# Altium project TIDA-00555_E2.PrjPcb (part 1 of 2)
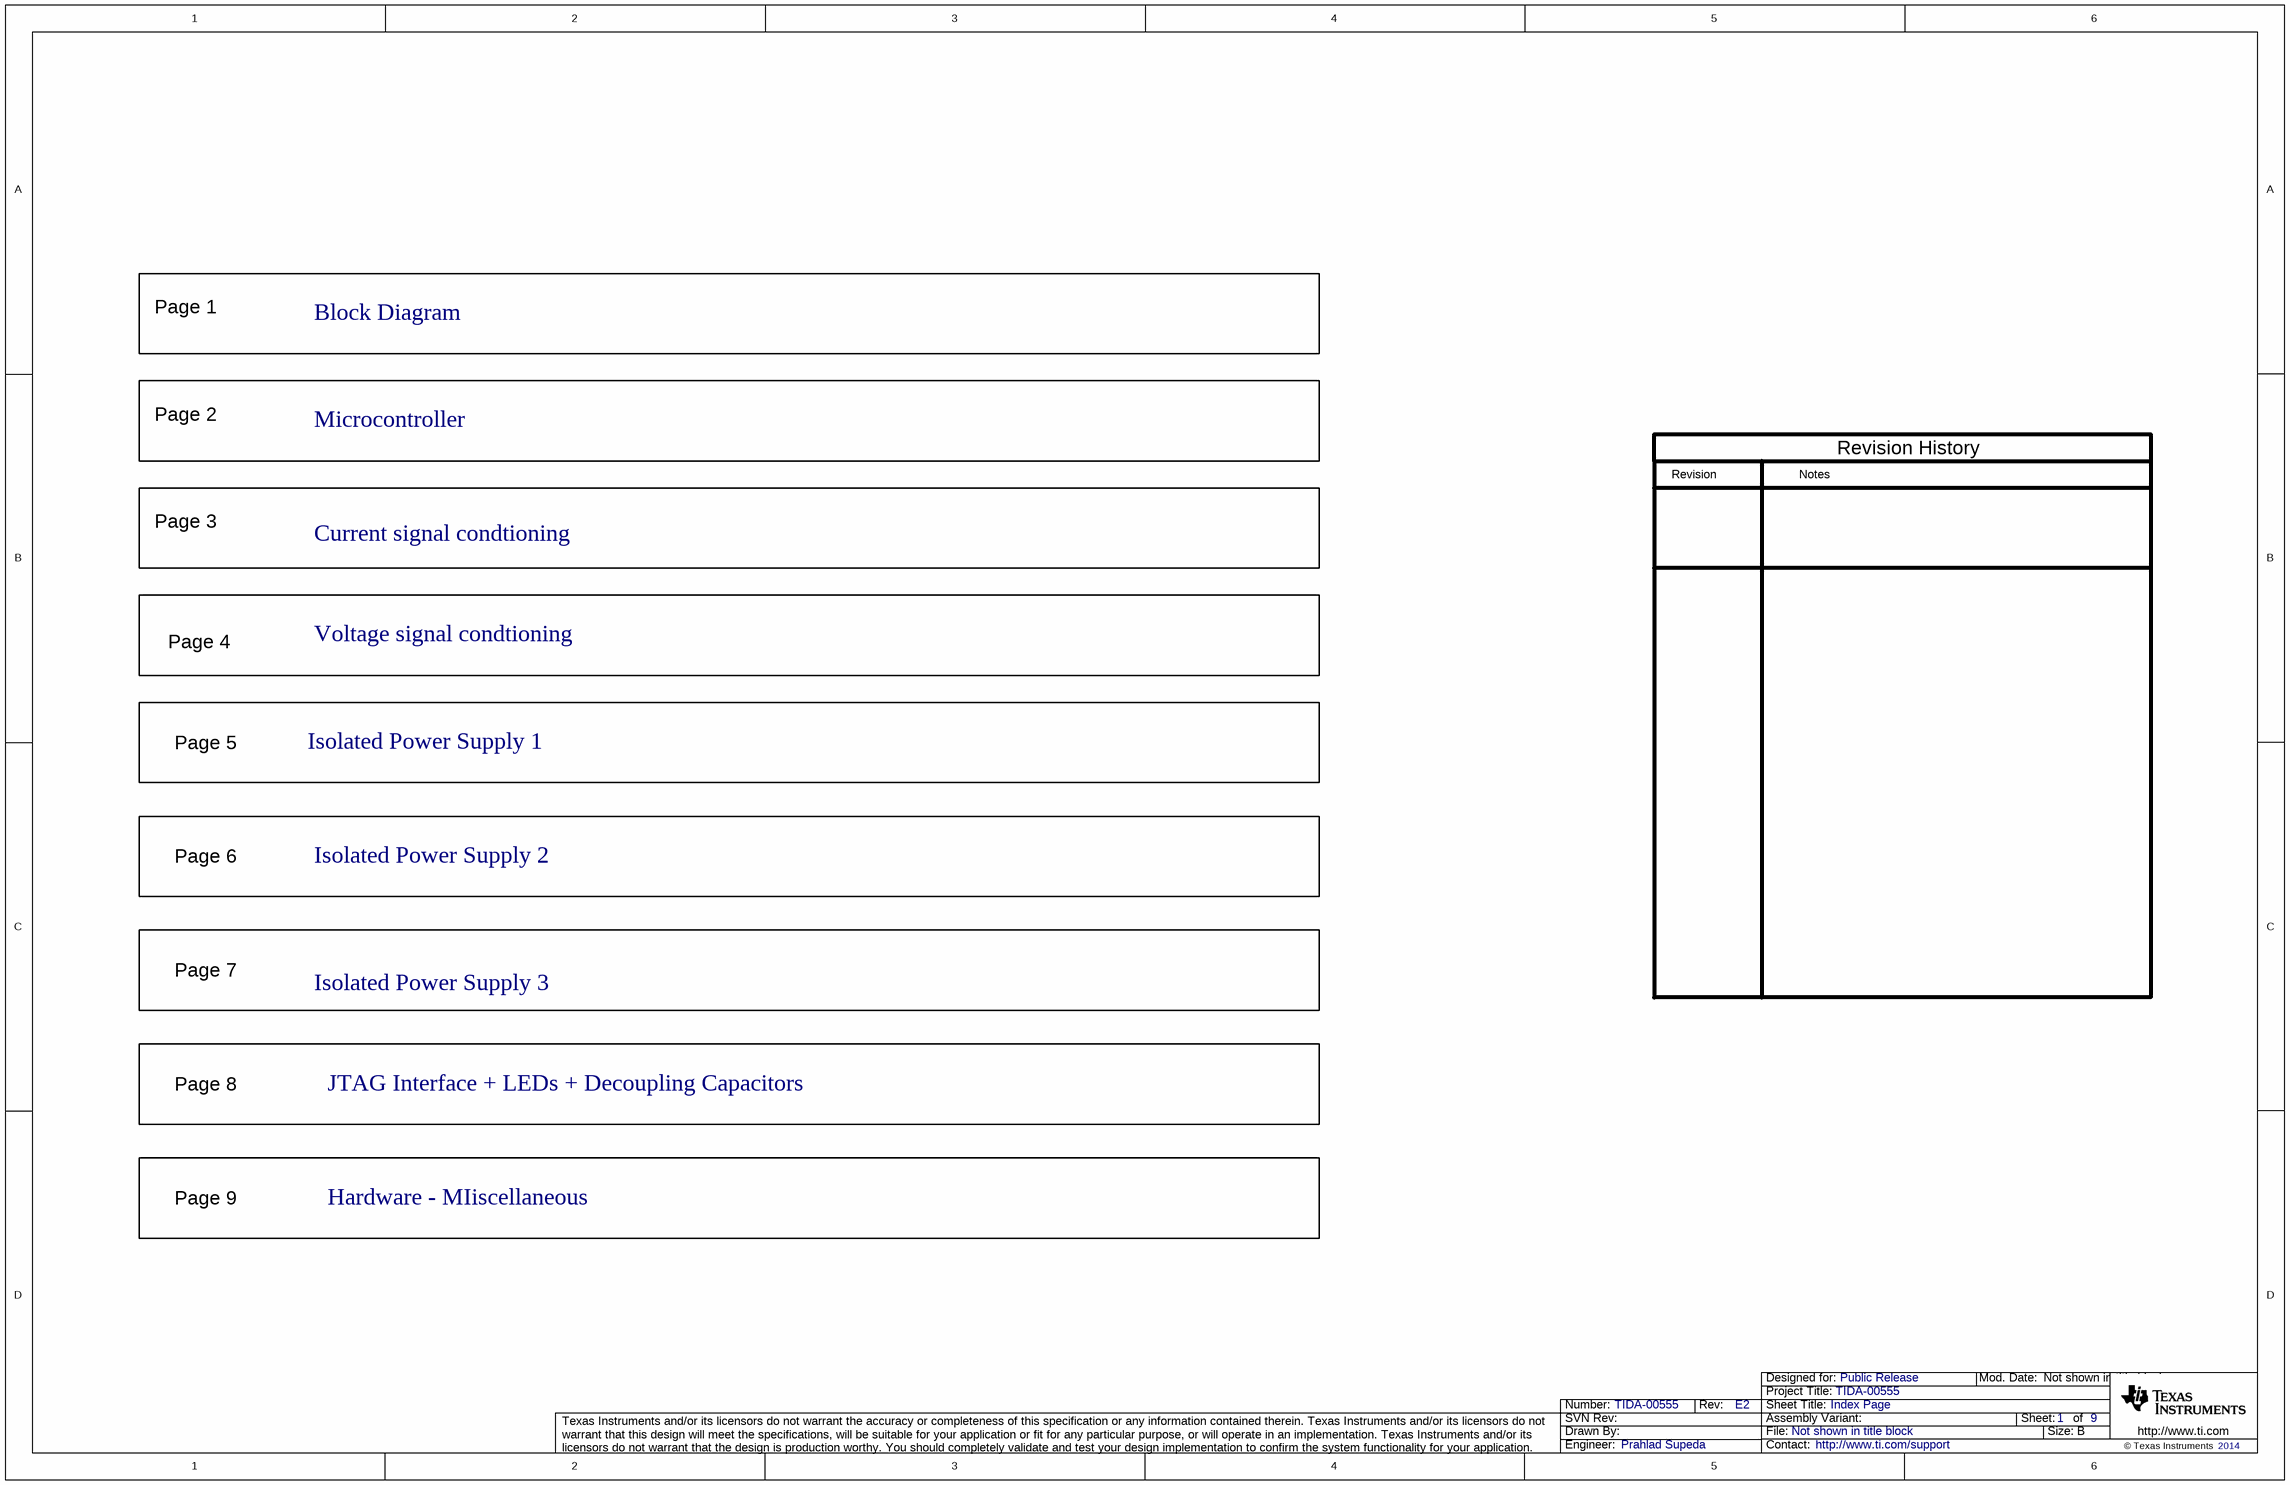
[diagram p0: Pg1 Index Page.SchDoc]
CopyrightYear: 2014; PCB_Layout: Anuradha; PCB_Rev: E2; PRJ_Customer: Public Release; PRJ_Engineer: Prahlad Supeda; PRJ_Number: TIDA-00555; PRJ_Title: TIDA-00555; SCH_Rev: E2; TechSupport: http://www.ti.com/support
9 sheets, 377 parts. Net scope: flat (ports and power ports of the same name join across sheets).
Board file: TIDA-00555_E2.PcbDoc
Sheets:
  Pg1 Index Page.SchDoc
  Pg2 Block Diagram.SchDoc
  Pg3-Microcontroller.SchDoc
  Pg4-Current  signal condtioning.SchDoc
  Pg5-Voltage signal condtioning.SchDoc
  Pg6-Power supply 1.SchDoc
  Pg7-Power supply 2.SchDoc
  Pg8.JTAG Interface + LEDs + Decoupling Capacitors.SchDoc
  Pg9-Hardware.SchDoc

## Sheet Pg1 Index Page.SchDoc: Index Page
size 431 x 279 mm; Date: Not shown in title block; ApprovedBy: Not shown in title block; CheckedBy: Not shown in title block; Author: Not shown in title block; CompanyName: Not shown in title block; Engineer: Not shown in title block; Organization: Not shown in title block; Address1: Not shown in title block; Address2: Not shown in title block; Address3: Not shown in title block; Address4: Not shown in title block; DocumentNumber: 1; Revision: Use project parameter SCH_Rev; SheetNumber: 1; SheetTotal: 9; PageSetup: Record=PageOptions¦CenterHorizontal=True¦CenterVertical=True¦PrintScale=1.00¦XCorrection=1.00¦YCorrection=1.00¦PrintKind=0¦BorderSize=5000000¦LeftOffset=0¦BottomOffset=0¦Orientation=2¦PaperLength=1000¦PaperWidth=1000¦Scale=100¦PaperSource=15¦PrintQuality=600¦MediaType=1¦DitherType=10¦PaperKind=Letter¦PrintScaleMode=1

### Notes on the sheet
- Page 1
- Block Diagram
- Page 2
- Microcontroller
- Revision
- Notes
- Revision History
- Page 3
- Current signal condtioning
- Page 4
- Voltage signal condtioning
- Page 5
- Isolated Power Supply 1
- Page 6
- Isolated Power Supply 2
- Page 7
- Isolated Power Supply 3
- Page 8
- JTAG Interface + LEDs + Decoupling Capacitors
- Page 9
- Hardware - MIiscellaneous

## Sheet Pg2 Block Diagram.SchDoc: Block Diagram
size 431 x 279 mm; Date: Not shown in title block; ApprovedBy: Not shown in title block; CheckedBy: Not shown in title block; Author: Not shown in title block; CompanyName: Not shown in title block; Engineer: Not shown in title block; Organization: Not shown in title block; Address1: Not shown in title block; Address2: Not shown in title block; Address3: Not shown in title block; Address4: Not shown in title block; DocumentNumber: 2; Revision: Use project parameter SCH_Rev; SheetNumber: 2; SheetTotal: 9; PageSetup: Record=PageOptions¦CenterHorizontal=True¦CenterVertical=True¦PrintScale=1.00¦XCorrection=1.00¦YCorrection=1.00¦PrintKind=0¦BorderSize=5000000¦LeftOffset=0¦BottomOffset=0¦Orientation=2¦PaperLength=1000¦PaperWidth=1000¦Scale=100¦PaperSource=15¦PrintQuality=600¦MediaType=1¦DitherType=10¦PaperKind=Letter¦PrintScaleMode=1
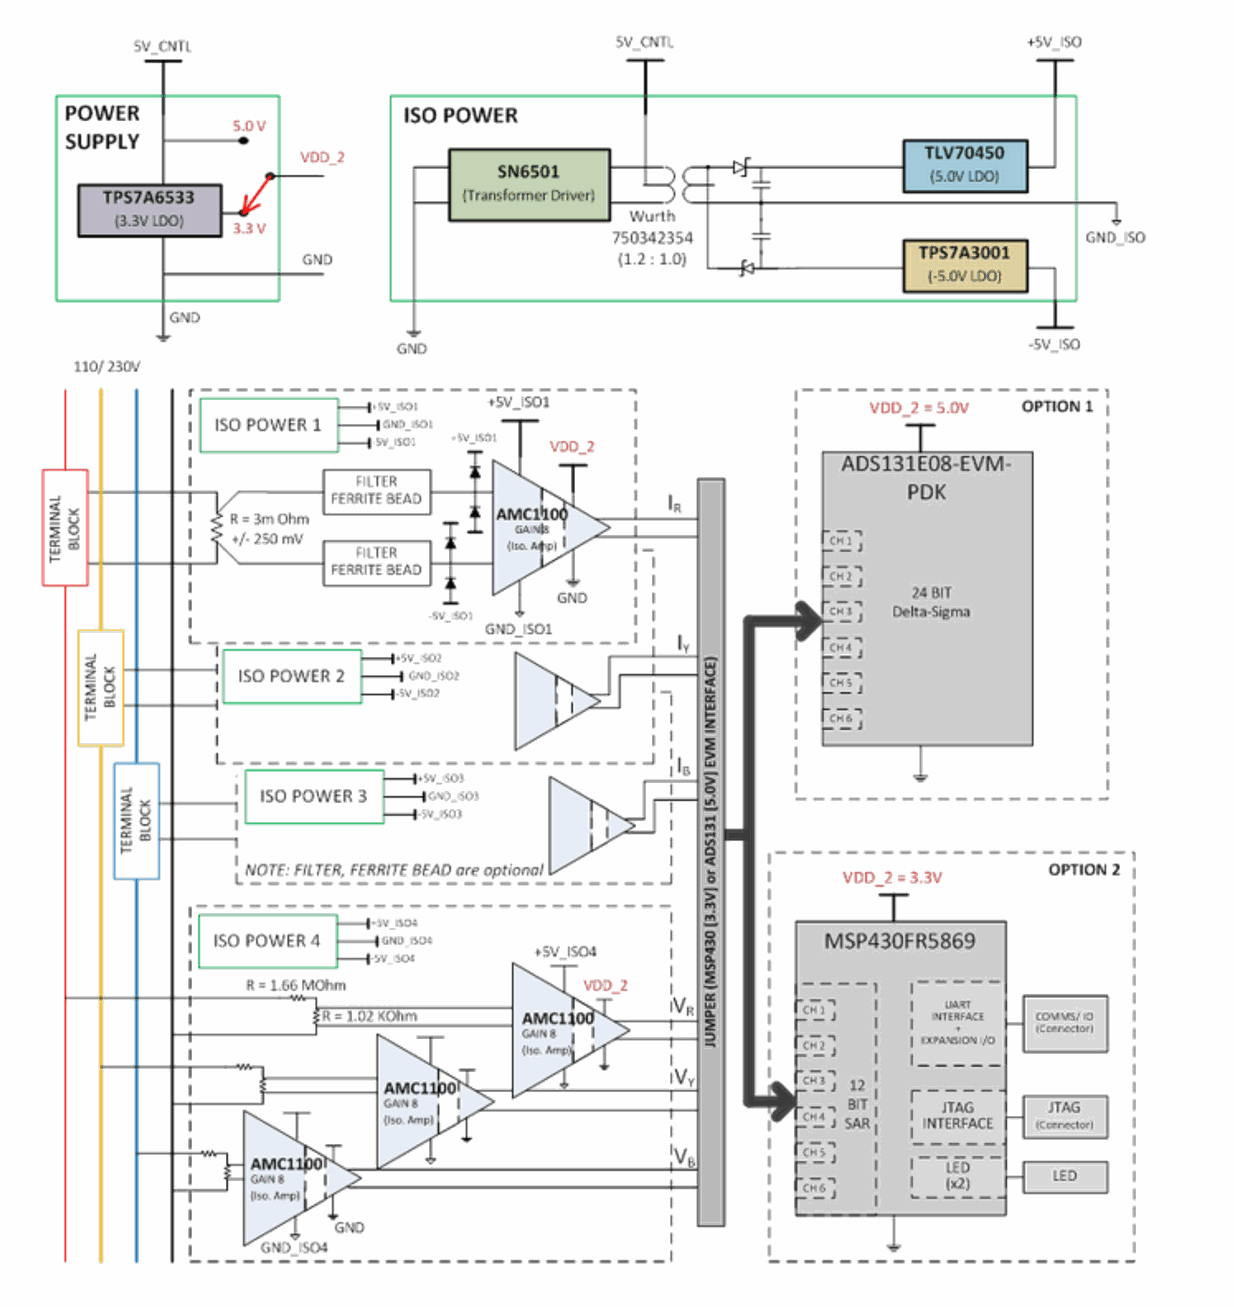
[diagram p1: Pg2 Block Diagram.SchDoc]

## Sheet Pg3-Microcontroller.SchDoc: MSP430F6779 + Crystal
size 431 x 279 mm; Date: Not shown in title block; ApprovedBy: Not shown in title block; CheckedBy: Not shown in title block; Author: Not shown in title block; CompanyName: Not shown in title block; Engineer: Not shown in title block; Organization: Not shown in title block; Address1: Not shown in title block; Address2: Not shown in title block; Address3: Not shown in title block; Address4: Not shown in title block; DocumentNumber: 6; Revision: Use project parameter SCH_Rev; SheetNumber: 3; SheetTotal: 9; PageSetup: Record=PageOptions¦CenterHorizontal=True¦CenterVertical=True¦PrintScale=1.00¦XCorrection=1.00¦YCorrection=1.00¦PrintKind=0¦BorderSize=5000000¦LeftOffset=0¦BottomOffset=0¦Orientation=2¦PaperLength=1000¦PaperWidth=1000¦Scale=100¦PaperSource=15¦PrintQuality=600¦MediaType=1¦DitherType=10¦PaperKind=Letter¦PrintScaleMode=1
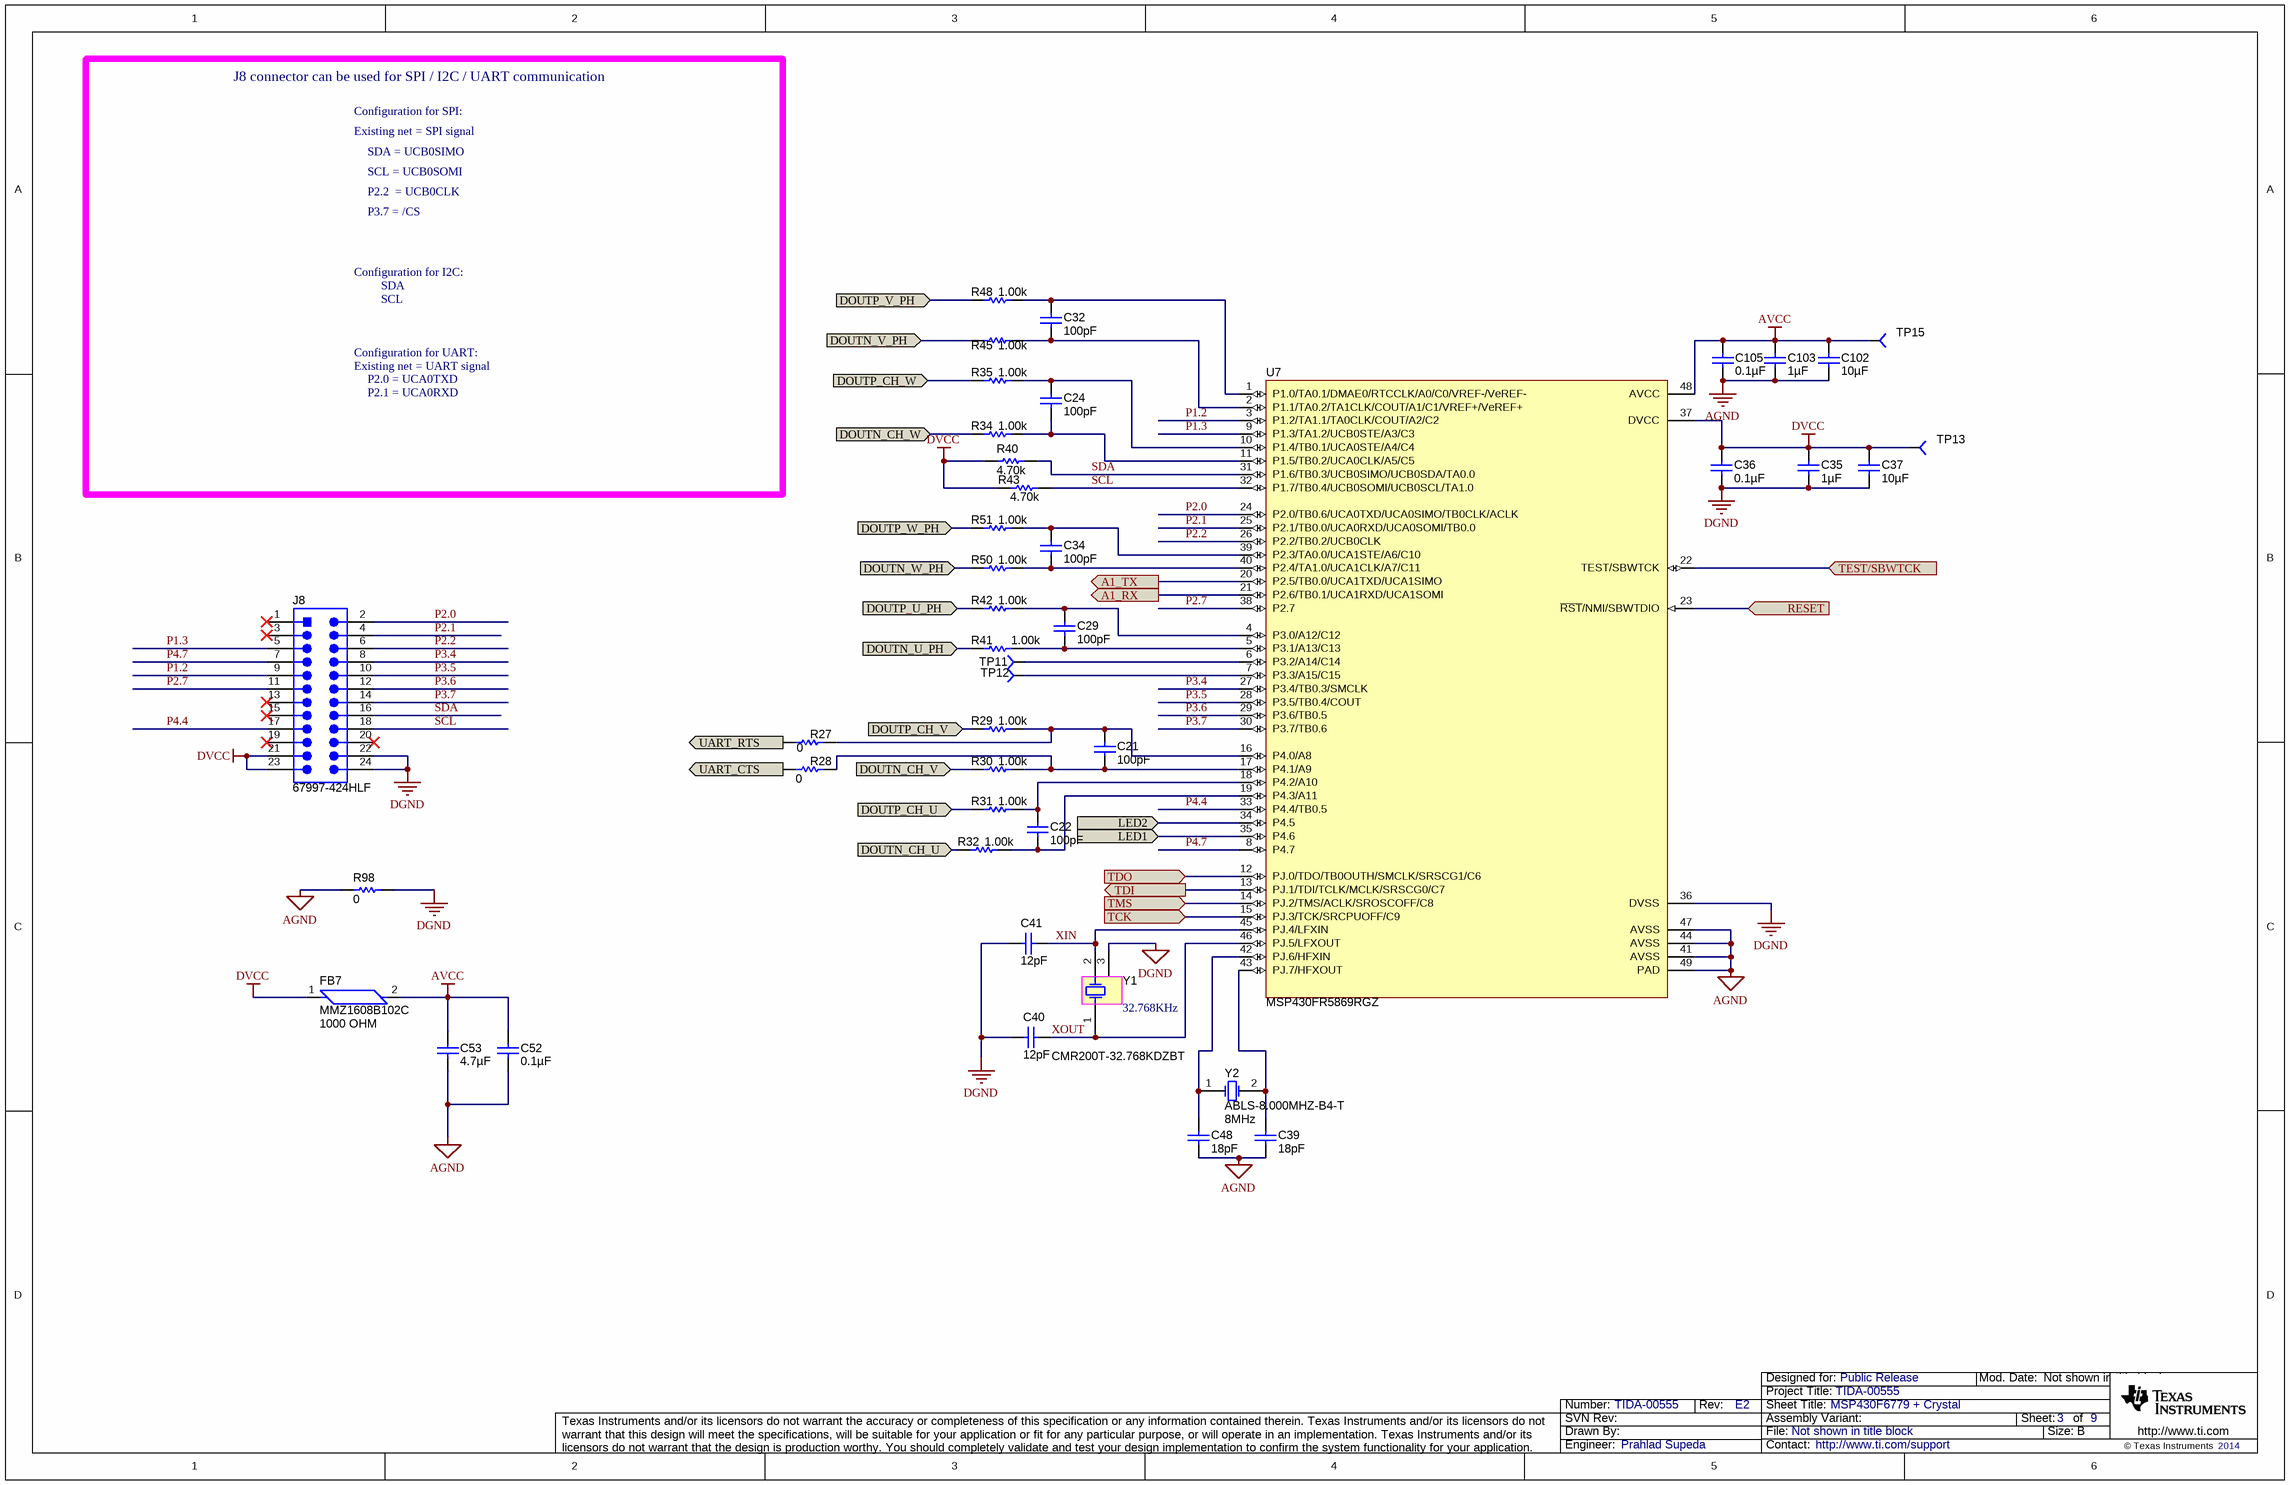
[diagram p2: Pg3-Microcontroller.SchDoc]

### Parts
C21  ValueDisplayed: 100pF  [0603]  (hidden comment: C0603C101J5GAC)
C22  ValueDisplayed: 100pF  [0603]  (hidden comment: C0603C101J5GAC)
C24  ValueDisplayed: 100pF  [0603]  (hidden comment: C0603C101J5GAC)
C29  ValueDisplayed: 100pF  [0603]  (hidden comment: C0603C101J5GAC)
C32  ValueDisplayed: 100pF  [0603]  (hidden comment: C0603C101J5GAC)
C34  ValueDisplayed: 100pF  [0603]  (hidden comment: C0603C101J5GAC)
C35  ValueDisplayed: 1µF  [0603]  (hidden comment: GRM188R71C105KA12D)
C36  ValueDisplayed: 0.1µF  [0603]  (hidden comment: 0603YC104JAT2A)
C37  ValueDisplayed: 10µF  [0603]  (hidden comment: GRM188R61E106MA73)
C39  ValueDisplayed: 18pF  [0603]  (hidden comment: GRM1885C1H180JA01D)
C40  ValueDisplayed: 12pF  [0603]  (hidden comment: 06035A120JAT2A)
C41  ValueDisplayed: 12pF  [0603]  (hidden comment: 06035A120JAT2A)
C48  ValueDisplayed: 18pF  [0603]  (hidden comment: GRM1885C1H180JA01D)
C52  ValueDisplayed: 0.1µF  [0603]  (hidden comment: 06033C104JAT2A)
C53  ValueDisplayed: 4.7µF  [0603]  (hidden comment: 0603ZD475KAT2A)
C102  ValueDisplayed: 10µF  [0603]  (hidden comment: GRM188R61E106MA73)
C103  ValueDisplayed: 1µF  [0603]  (hidden comment: GRM188R71C105KA12D)
C105  ValueDisplayed: 0.1µF  [0603]  (hidden comment: 0603YC104JAT2A)
FB7  MMZ1608B102C  value 1000 OHM  [FB0603]
J8  67997-424HLF  [TSW-112-07-G-D]
R27  value 0  [0603]  (hidden comment: CRCW06030000Z0EA)
R28  value 0  [0603]  (hidden comment: CRCW06030000Z0EA)
R29  ValueDisplayed: 1.00k  [0603]  (hidden comment: RG1608P-102-B-T5)
R30  ValueDisplayed: 1.00k  [0603]  (hidden comment: RG1608P-102-B-T5)
R31  ValueDisplayed: 1.00k  [0603]  (hidden comment: RG1608P-102-B-T5)
R32  ValueDisplayed: 1.00k  [0603]  (hidden comment: RG1608P-102-B-T5)
R34  ValueDisplayed: 1.00k  [0603]  (hidden comment: RG1608P-102-B-T5)
R35  ValueDisplayed: 1.00k  [0603]  (hidden comment: RG1608P-102-B-T5)
R40  value 4.70k  [0603]  (hidden comment: RC0603FR-074K7L)
R41  ValueDisplayed: 1.00k  [0603]  (hidden comment: RG1608P-102-B-T5)
R42  ValueDisplayed: 1.00k  [0603]  (hidden comment: RG1608P-102-B-T5)
R43  value 4.70k  [0603]  (hidden comment: RC0603FR-074K7L)
R45  ValueDisplayed: 1.00k  [0603]  (hidden comment: RG1608P-102-B-T5)
R48  ValueDisplayed: 1.00k  [0603]  (hidden comment: RG1608P-102-B-T5)
R50  ValueDisplayed: 1.00k  [0603]  (hidden comment: RG1608P-102-B-T5)
R51  ValueDisplayed: 1.00k  [0603]  (hidden comment: RG1608P-102-B-T5)
R98  value 0  [0805_HV]  (hidden comment: CRCW08050000Z0EA)
TP11  TP-040_RND  [TP-040_RND]  (value not drawn)
TP12  TP-040_RND  [TP-040_RND]  (value not drawn)
TP13  TP-040_RND  [TP-040_RND]  (value not drawn)
TP15  TP-040_RND  [TP-040_RND]  (value not drawn)
U7  MSP430FR5869RGZ  [RGZ0048B]
Y1  CMR200T-32.768KDZBT  Frequency: 32.768KHz  [XTAL_CMR200T]
Y2  ABLS-8.000MHZ-B4-T  Frequency: 8MHz  [XTAL_CSM-7X]

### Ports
A1_RX (out), A1_TX (out), DOUTN_CH_U (in), DOUTN_CH_V (in), DOUTN_CH_W (in), DOUTN_U_PH (in), DOUTN_V_PH (in), DOUTN_W_PH (in), DOUTP_CH_U (in), DOUTP_CH_V (in), DOUTP_CH_W (in), DOUTP_U_PH (in), DOUTP_V_PH (in), DOUTP_W_PH (in), LED1 (in), LED2 (in), RESET, TCK, TDI (out), TDO, TEST/SBWTCK, TMS, UART_CTS, UART_RTS

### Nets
AGND: C39.2 C48.2 C52.2 C53.2 C102.2 C103.2 C105.2 R98.1 U7.41(AVSS) U7.44(AVSS) U7.47(AVSS) U7.49(PAD)
AVCC: C52.1 C53.1 C102.1 C103.1 C105.1 FB7.2 TP15.1 U7.48(AVCC)
DGND: C35.2 C36.2 C37.2 C40.2 C41.2 J8.22 J8.24 R98.2 U7.36(DVSS) Y1.3
DVCC: C35.1 C36.1 C37.1 FB7.1 J8.21 J8.23 R40.1 R43.1 TP13.1 U7.37(DVCC)
A1_RX: U7.21(P2.6/TB0.1/UCA1RXD/UCA1SOMI) ; port A1_RX
A1_TX: U7.20(P2.5/TB0.0/UCA1TXD/UCA1SIMO) ; port A1_TX
DOUTN_CH_U: R32.1 ; port DOUTN_CH_U
DOUTN_CH_V: R30.1 ; port DOUTN_CH_V
DOUTN_CH_W: R34.1 ; port DOUTN_CH_W
DOUTN_U_PH: R41.1 ; port DOUTN_U_PH
DOUTN_V_PH: R45.1 ; port DOUTN_V_PH
DOUTN_W_PH: R50.1 ; port DOUTN_W_PH
DOUTP_CH_U: R31.1 ; port DOUTP_CH_U
DOUTP_CH_V: R29.1 ; port DOUTP_CH_V
DOUTP_CH_W: R35.1 ; port DOUTP_CH_W
DOUTP_U_PH: R42.1 ; port DOUTP_U_PH
DOUTP_V_PH: R48.1 ; port DOUTP_V_PH
DOUTP_W_PH: R51.1 ; port DOUTP_W_PH
LED1: U7.35(P4.6) ; port LED1
LED2: U7.34(P4.5) ; port LED2
P1.2: J8.9 U7.3(P1.2/TA1.1/TA0CLK/COUT/A2/C2)
P1.3: J8.5 U7.9(P1.3/TA1.2/UCB0STE/A3/C3)
P2.0: J8.2 U7.24(P2.0/TB0.6/UCA0TXD/UCA0SIMO/TB0CLK/ACLK)
P2.1: J8.4 U7.25(P2.1/TB0.0/UCA0RXD/UCA0SOMI/TB0.0)
P2.2: J8.6 U7.26(P2.2/TB0.2/UCB0CLK)
P2.7: J8.11 U7.38(P2.7)
P3.4: J8.8 U7.27(P3.4/TB0.3/SMCLK)
P3.5: J8.10 U7.28(P3.5/TB0.4/COUT)
P3.6: J8.12 U7.29(P3.6/TB0.5)
P3.7: J8.14 U7.30(P3.7/TB0.6)
P4.4: J8.17 U7.33(P4.4/TB0.5)
P4.7: J8.7 U7.8(P4.7)
RESET: U7.23(~{RST}/NMI/SBWTDIO) ; port RESET
SCL: J8.18 R43.2 U7.32(P1.7/TB0.4/UCB0SOMI/UCB0SCL/TA1.0)
SDA: J8.16 R40.2 U7.31(P1.6/TB0.3/UCB0SIMO/UCB0SDA/TA0.0)
TCK: U7.15(PJ.3/TCK/SRCPUOFF/C9) ; port TCK
TDI: U7.13(PJ.1/TDI/TCLK/MCLK/SRSCG0/C7) ; port TDI
TDO: U7.12(PJ.0/TDO/TB0OUTH/SMCLK/SRSCG1/C6) ; port TDO
TEST/SBWTCK: U7.22(TEST/SBWTCK) ; port TEST/SBWTCK
TMS: U7.14(PJ.2/TMS/ACLK/SROSCOFF/C8) ; port TMS
UART_CTS: R28.1 ; port UART_CTS
UART_RTS: R27.1 ; port UART_RTS
XIN: C41.1 U7.45(PJ.4/LFXIN) Y1.2
XOUT: C40.1 U7.46(PJ.5/LFXOUT) Y1.1
NetC21_1: C21.1 R28.2 R30.2 U7.17(P4.1/A9)
NetC21_2: C21.2 R27.2 R29.2 U7.16(P4.0/A8)
NetC22_1: C22.1 R32.2 U7.19(P4.3/A11)
NetC22_2: C22.2 R31.2 U7.18(P4.2/A10)
NetC24_1: C24.1 R34.2 U7.11(P1.5/TB0.2/UCA0CLK/A5/C5)
NetC24_2: C24.2 R35.2 U7.10(P1.4/TB0.1/UCA0STE/A4/C4)
NetC29_1: C29.1 R41.2 U7.5(P3.1/A13/C13)
NetC29_2: C29.2 R42.2 U7.4(P3.0/A12/C12)
NetC32_1: C32.1 R45.2 U7.2(P1.1/TA0.2/TA1CLK/COUT/A1/C1/VREF+/VeREF+)
NetC32_2: C32.2 R48.2 U7.1(P1.0/TA0.1/DMAE0/RTCCLK/A0/C0/VREF-/VeREF-)
NetC34_1: C34.1 R50.2 U7.40(P2.4/TA1.0/UCA1CLK/A7/C11)
NetC34_2: C34.2 R51.2 U7.39(P2.3/TA0.0/UCA1STE/A6/C10)
NetC39_1: C39.1 U7.43(PJ.7/HFXOUT) Y2.2(OSC2)
NetC48_1: C48.1 U7.42(PJ.6/HFXIN) Y2.1(OSC1)
NetTP11_1: TP11.1 U7.6(P3.2/A14/C14)
NetTP12_1: TP12.1 U7.7(P3.3/A15/C15)

Not connected (* = marked no-connect by the designer): J8 1* 3* 13* 15* 19* 20*

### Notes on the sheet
- J8 connector can be used for SPI / I2C / UART communication
- Configuration for SPI:
- Existing net = SPI signal
- SDA = UCB0SIMO
- SCL = UCB0SOMI
- P2.2  = UCB0CLK
- P3.7 = /CS
- Configuration for I2C:
- SDA
- SCL
- Configuration for UART:
- Existing net = UART signal
- P2.0 = UCA0TXD
- P2.1 = UCA0RXD

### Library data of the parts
C21 C22 C24 C29 C32 C34 = C0603C101J5GAC: CAP, CERM, 100 pF, 50 V, +/- 5%, C0G/NP0, 0603; Manufacturer: Kemet; Polarized: N; CompType: Capacitor; Value: 100pF; U/M: EA; Cap_F: 0.0000000001; Tolerance_%: 5; Value1: Unknown; VDC_V: 50; Value2: 50V; TaMin_C: -55; TaMax_C: 125
C35 C103 = GRM188R71C105KA12D: CAP, CERM, 1 µF, 16 V, +/- 10%, X7R, 0603; Manufacturer: MuRata; Polarized: N; CompType: Capacitor; Value: 1uF; U/M: EA; Cap_F: 0.000001; Tolerance_%: 10; ESR_ohm: 0.011; Value1: 0.011 ohm; VDC_V: 16; Value2: 16V; TaMin_C: -55; TaMax_C: 125
C36 C105 = 0603YC104JAT2A: CAP, CERM, 0.1 µF, 16 V, +/- 5%, X7R, 0603; Manufacturer: AVX; Polarized: N; CompType: Capacitor; Value: 0.1uF; U/M: EA; Cap_F: 0.0000001; Tolerance_%: 5; ESR_ohm: 0.039; Value1: 0.039 ohm; VDC_V: 16; Value2: 16V; TaMin_C: -55; TaMax_C: 125
C37 C102 = GRM188R61E106MA73: CAP, CERM, 10uF, 25V, +/-20%, X5R, 0603; Manufacturer: MuRata; Polarized: N; CompType: Capacitor; U/M: EA; Cap_F: 0.00001; Tolerance_%: 20; Value1: Unknown; VDC_V: 25; TaMin_C: -55; TaMax_C: 85
C39 C48 = GRM1885C1H180JA01D: CAP, CERM, 18pF, 50V, +/-5%, C0G/NP0, 0603; Manufacturer: MuRata; Polarized: N; CompType: Capacitor; U/M: EA; Cap_F: 0.000000000018; Tolerance_%: 5; Value1: Unknown; VDC_V: 50; TaMin_C: -55; TaMax_C: 125
C40 C41 = 06035A120JAT2A: CAP, CERM, 12pF, 50V, +/-5%, C0G/NP0, 0603; Manufacturer: AVX; Polarized: N; CompType: Capacitor; U/M: EA; Cap_F: 0.000000000012; Tolerance_%: 5; ESR_Ohm: 0.363; Value1: 0.363 ohm; VDC_V: 50; TaMin_C: -55; TaMax_C: 125
C52 = 06033C104JAT2A: CAP, CERM, 0.1uF, 25V, +/-5%, X7R, 0603; Manufacturer: AVX; Polarized: N; CompType: Capacitor; U/M: EA; Cap_F: 0.0000001; Tolerance_%: 5; ESR_Ohm: 0.05; Value1: 0.05 ohm; VDC_V: 25; TaMin_C: -55; TaMax_C: 125
C53 = 0603ZD475KAT2A: CAP, CERM, 4.7uF, 10V, +/-10%, X5R, 0603; Manufacturer: AVX; Polarized: N; CompType: Capacitor; U/M: EA; Cap_F: 0.0000047; Tolerance_%: 10; Value1: Unknown; TaMin_C: -55; TaMax_C: 85
FB7 = MMZ1608B102C: FERRITE CHIP 1000 OHM 300MA 0603; Manufacturer: TDK Corporation; CompType: Ferrite Bead
J8 = TSW-112-07-G-D: Header, TH, 100mil, 12x2, Gold plated, 230 mil above insulator; Manufacturer: FCI; SymbolCreator: a0412235; U/M: EA
R27 R28 = CRCW06030000Z0EA: RES, 0 ohm, 5%, 0.1W, 0603; Manufacturer: Vishay-Dale; CompType: Resistor; Value_Code: 0000; Tolerance_%: 5; Power_W: 0.1; VDC_V: 75; TempCo: 200 ppm/C; EIA_Code: E24; U/M: EA
R29-R32 R34 R35 R41 R42 R45 R48 R50 R51 = RG1608P-102-B-T5: RES, 1.00 k, 0.1%, 0.1 W, 0603; Manufacturer: Susumu Co Ltd; CompType: Resistor; Value: 1.00k; Res_ohm: 1000; Value_Code: 1k00; Tolerance_%: 0.1; Value2: 0.1W; VDC_V: 75; TempCo: 25 ppm/C; EIA_Code: E192; U/M: EA
R40 R43 = RC0603FR-074K7L: RES, 4.70k ohm, 1%, 0.1W, 0603; Manufacturer: Yageo America; CompType: Resistor; Res_ohm: 4700; Value_Code: 4k70; Tolerance_%: 1; Power_W: 0.1; VDC_V: 150; TempCo: 200 ppm/C; U/M: EA
R98 = CRCW0805330KJNEA: RES, 0 ohm, 5%, 0.125W, 0805; Manufacturer: Vishay-Dale; CompType: Resistor; Tolerance_%: 5; Power_W: 0.125; VDC_V: 150; TempCo: 200 ppm/C; EIA_Code: E24; U/M: EA
TP11-TP13 TP15 = TP-040_RND: Test Point, O.040 Hole; Manufacturer: STD; Value: STD
U7 = MSP430FR5969IRGZ: Mixed Signal Microcontroller, RGZ0048B; Manufacturer: Texas Instruments; SymbolCreator: a0411947; CompType: IC; U/M: EA
Y1 = CMR200T-32.768KDZBT: CRYSTAL, 32.768KHz, 6PF, +/- 20PPM, SMD-3P; Manufacturer: CITIZEN; SymbolCreator: x0199378
Y2 = ABLS-8.000MHZ-B4-T: Crystal, 8MHz, 18pF, SMD; Manufacturer: Abracon Corportation; SymbolCreator: a0412235; U/M: EA; TaMin_C: 0; TaMax_C: 70; Frequency Stability: ±50ppm

## Sheet Pg4-Current  signal condtioning.SchDoc: Analog Front End (Current) + Delfino Interface
size 431 x 279 mm; Date: Not shown in title block; ApprovedBy: Not shown in title block; CheckedBy: Not shown in title block; Author: Not shown in title block; CompanyName: Not shown in title block; Engineer: Not shown in title block; Organization: Not shown in title block; Address1: Not shown in title block; Address2: Not shown in title block; Address3: Not shown in title block; Address4: Not shown in title block; DocumentNumber: 3; Revision: Use project parameter SCH_Rev; SheetNumber: 4; SheetTotal: 9; PageSetup: Record=PageOptions¦CenterHorizontal=True¦CenterVertical=True¦PrintScale=0.62¦XCorrection=1.00¦YCorrection=1.00¦PrintKind=0¦BorderSize=5000000¦LeftOffset=0¦BottomOffset=0¦Orientation=2¦PaperLength=1000¦PaperWidth=1000¦Scale=100¦PaperSource=15¦PrintQuality=600¦MediaType=1¦DitherType=10¦PaperKind=Letter¦PrintScaleMode=1
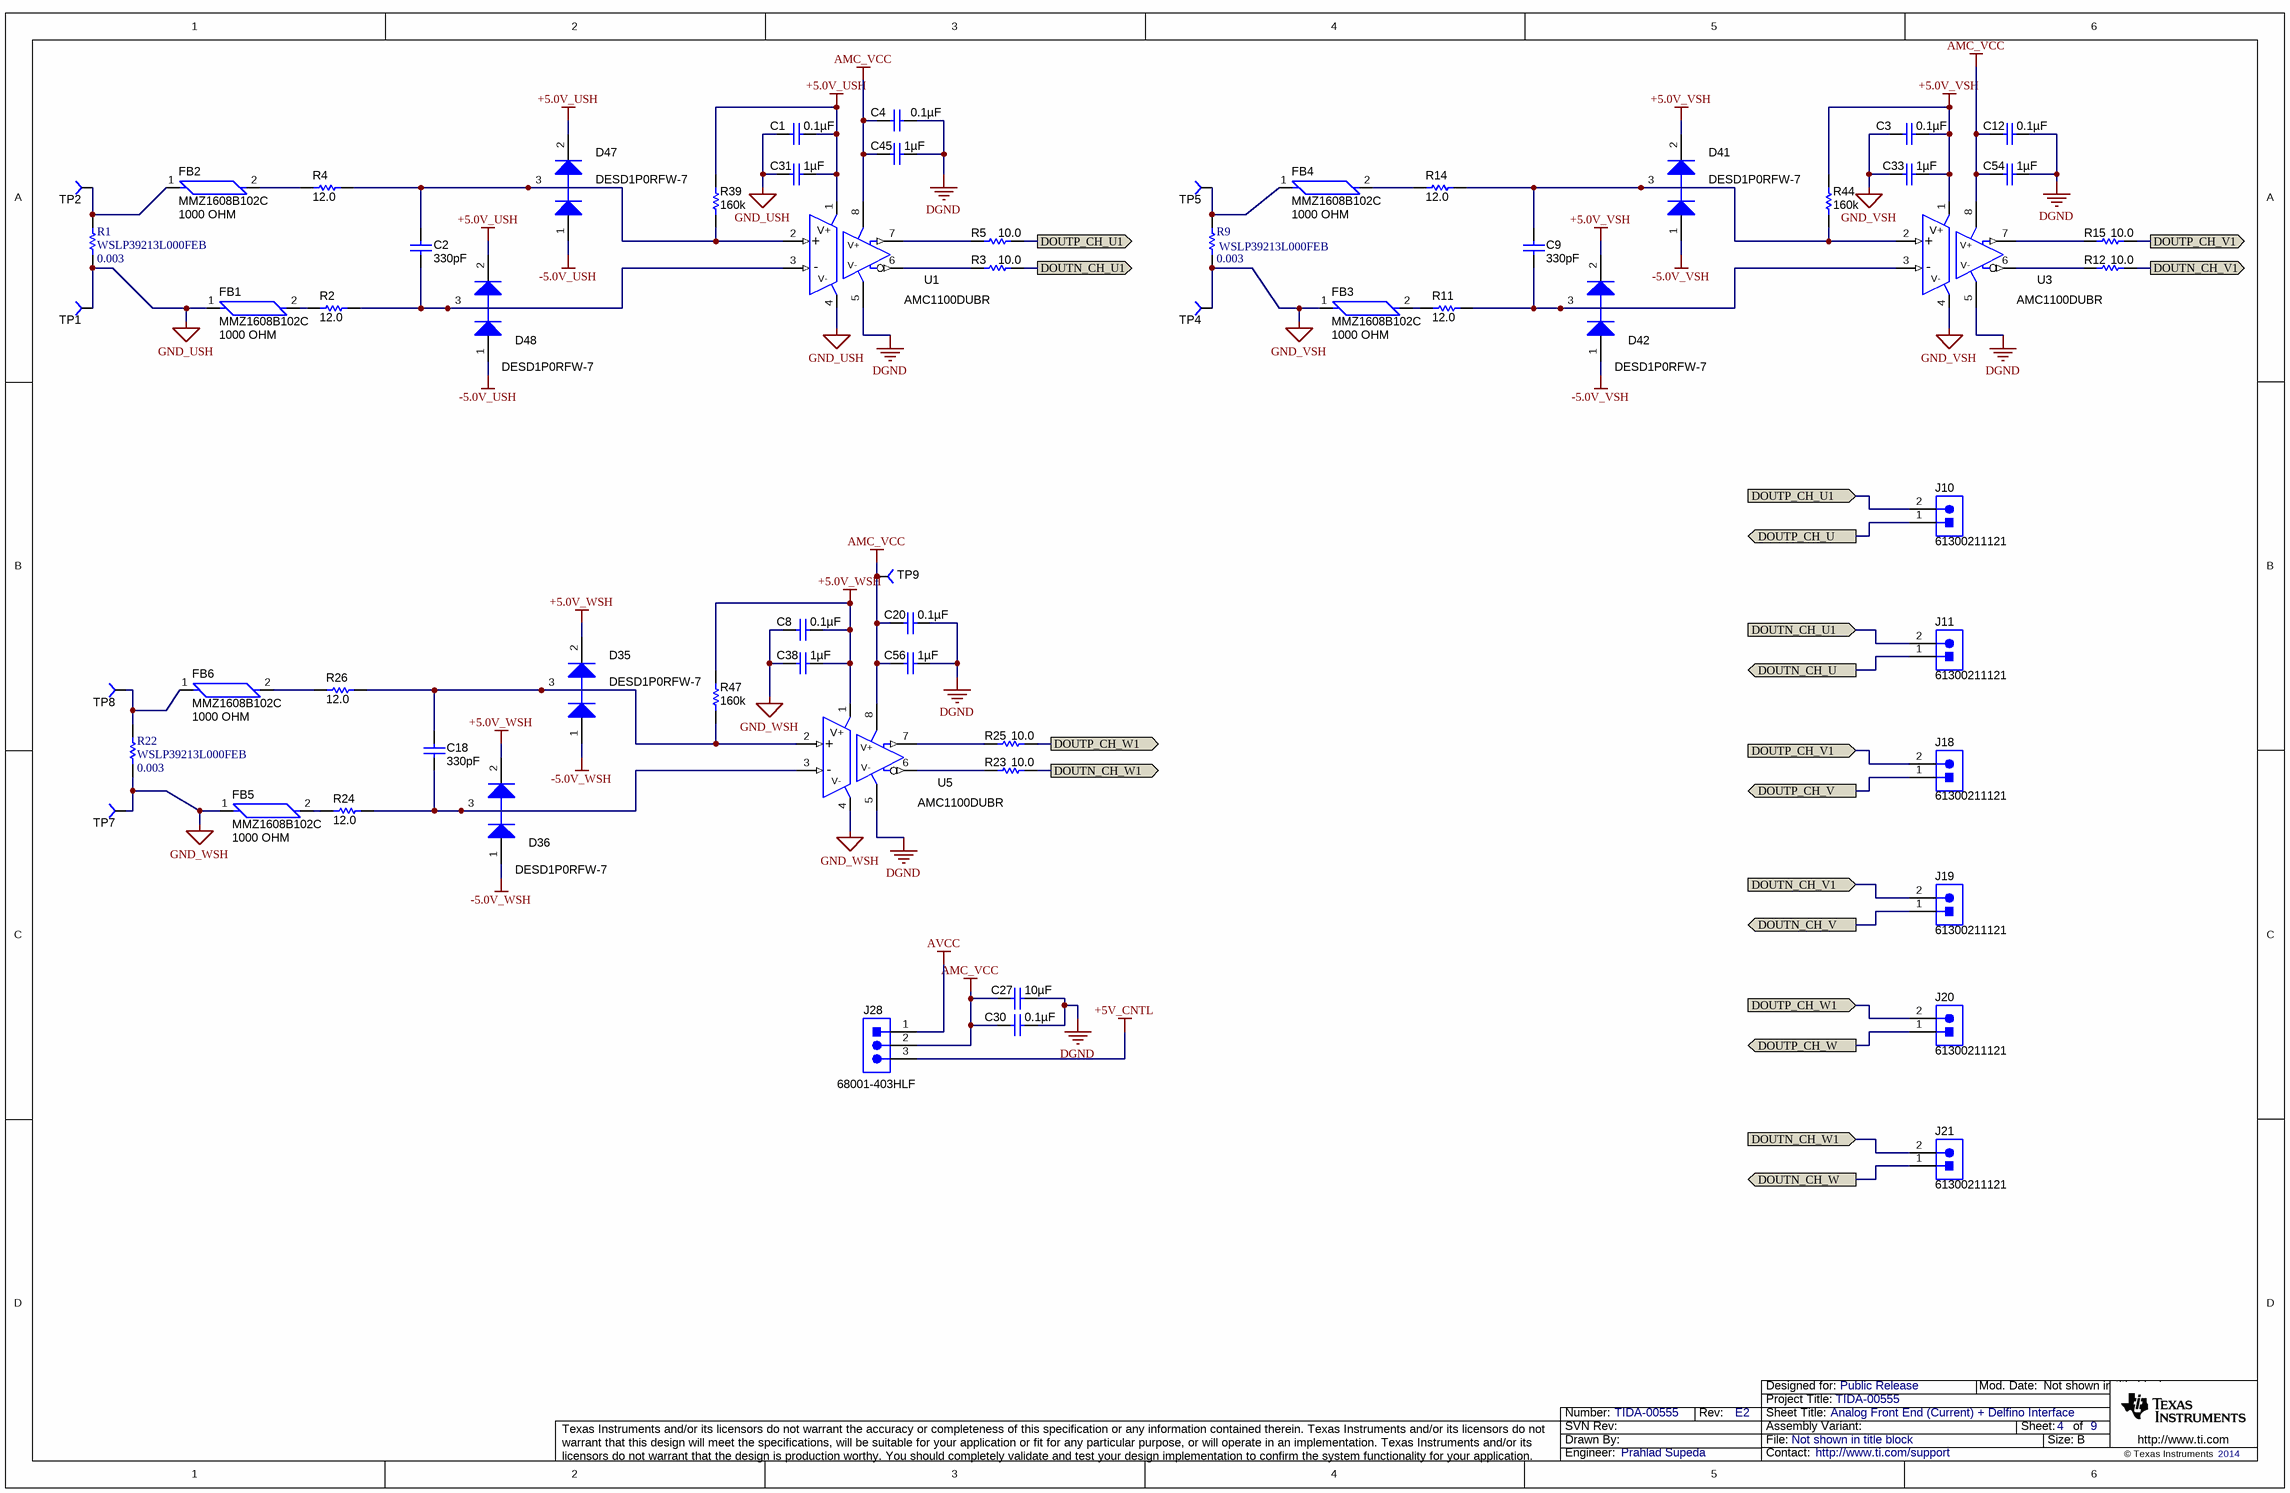
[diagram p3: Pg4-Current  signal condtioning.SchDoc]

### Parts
C1  ValueDisplayed: 0.1µF  [0603]
C2  ValueDisplayed: 330pF  [0805_HV]  (hidden comment: 08055A331KAT2A)
C3  ValueDisplayed: 0.1µF  [0603]
C4  ValueDisplayed: 0.1µF  [0603]
C8  ValueDisplayed: 0.1µF  [0603]
C9  ValueDisplayed: 330pF  [0805_HV]  (hidden comment: 08055A331KAT2A)
C12  ValueDisplayed: 0.1µF  [0603]
C18  ValueDisplayed: 330pF  [0805_HV]  (hidden comment: 08055A331KAT2A)
C20  ValueDisplayed: 0.1µF  [0603]
C27  ValueDisplayed: 10µF  [1210]
C30  ValueDisplayed: 0.1µF  [0603]
C31  ValueDisplayed: 1µF  [0603]  (hidden comment: GRM188R71C105KA12D)
C33  ValueDisplayed: 1µF  [0603]  (hidden comment: GRM188R71C105KA12D)
C38  ValueDisplayed: 1µF  [0603]  (hidden comment: GRM188R71C105KA12D)
C45  ValueDisplayed: 1µF  [0603]  (hidden comment: GRM188R71C105KA12D)
C54  ValueDisplayed: 1µF  [0603]  (hidden comment: GRM188R71C105KA12D)
C56  ValueDisplayed: 1µF  [0603]  (hidden comment: GRM188R71C105KA12D)
D35  value DESD1P0RFW-7  [SOT-323]
D36  value DESD1P0RFW-7  [SOT-323]
D41  value DESD1P0RFW-7  [SOT-323]
D42  value DESD1P0RFW-7  [SOT-323]
D47  value DESD1P0RFW-7  [SOT-323]
D48  value DESD1P0RFW-7  [SOT-323]
FB1  MMZ1608B102C  value 1000 OHM  [FB0603]
FB2  MMZ1608B102C  value 1000 OHM  [FB0603]
FB3  MMZ1608B102C  value 1000 OHM  [FB0603]
FB4  MMZ1608B102C  value 1000 OHM  [FB0603]
FB5  MMZ1608B102C  value 1000 OHM  [FB0603]
FB6  MMZ1608B102C  value 1000 OHM  [FB0603]
J10  61300211121  [WURTH_61300211121]
J11  61300211121  [WURTH_61300211121]
J18  61300211121  [WURTH_61300211121]
J19  61300211121  [WURTH_61300211121]
J20  61300211121  [WURTH_61300211121]
J21  61300211121  [WURTH_61300211121]
J28  68001-403HLF  [HDR1X3]
R1  WSLP39213L000FEB  value 0.003  [RC3921]
R2  ValueDisplayed: 12.0  [0603]  (hidden comment: RC0603FR-0712RL)
R3  value 10.0  [0603]
R4  ValueDisplayed: 12.0  [0603]  (hidden comment: RC0603FR-0712RL)
R5  value 10.0  [0603]
R9  WSLP39213L000FEB  value 0.003  [RC3921]
R11  ValueDisplayed: 12.0  [0603]  (hidden comment: RC0603FR-0712RL)
R12  value 10.0  [0603]
R14  ValueDisplayed: 12.0  [0603]  (hidden comment: RC0603FR-0712RL)
R15  value 10.0  [0603]
R22  WSLP39213L000FEB  value 0.003  [RC3921]
R23  value 10.0  [0603]
R24  ValueDisplayed: 12.0  [0603]  (hidden comment: RC0603FR-0712RL)
R25  value 10.0  [0603]
R26  ValueDisplayed: 12.0  [0603]  (hidden comment: RC0603FR-0712RL)
R39  ValueDisplayed: 160k  [0603]  (hidden comment: CRCW0603160KFKEA)
R44  ValueDisplayed: 160k  [0603]  (hidden comment: CRCW0603160KFKEA)
R47  ValueDisplayed: 160k  [0603]  (hidden comment: CRCW0603160KFKEA)
TP1  TP-5001-BLACK  [TH-40]  (value not drawn)
TP2  TP-5001-BLACK  [TH-40]  (value not drawn)
TP4  TP-5001-BLACK  [TH-40]  (value not drawn)
TP5  TP-5001-BLACK  [TH-40]  (value not drawn)
TP7  TP-5001-BLACK  [TH-40]  (value not drawn)
TP8  TP-5001-BLACK  [TH-40]  (value not drawn)
TP9  (no value)  [TP-040_RND]
U1  AMC1100DUBR  [DUB0008A_N]
U3  AMC1100DUBR  [DUB0008A_N]
U5  AMC1100DUBR  [DUB0008A_N]

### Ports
DOUTN_CH_U1 (in), DOUTN_CH_U1 (out), DOUTN_CH_U (out), DOUTN_CH_V1 (in), DOUTN_CH_V1 (out), DOUTN_CH_V (out), DOUTN_CH_W1 (in), DOUTN_CH_W1 (out), DOUTN_CH_W (out), DOUTP_CH_U1 (in), DOUTP_CH_U1 (out), DOUTP_CH_U (out), DOUTP_CH_V1 (in), DOUTP_CH_V1 (out), DOUTP_CH_V (out), DOUTP_CH_W1 (in), DOUTP_CH_W1 (out), DOUTP_CH_W (out)

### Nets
+5.0V_USH: C1.1 C31.2 D47.2(K) D48.2(K) R39.2 U1.1(VDD1)
+5.0V_VSH: C3.1 C33.2 D41.2(K) D42.2(K) R44.2 U3.1(VDD1)
+5.0V_WSH: C8.1 C38.2 D35.2(K) D36.2(K) R47.2 U5.1(VDD1)
+5V_CNTL: J28.3
-5.0V_USH: D47.1(A) D48.1(A)
-5.0V_VSH: D41.1(A) D42.1(A)
-5.0V_WSH: D35.1(A) D36.1(A)
AMC_VCC: C4.2 C12.2 C20.2 C27.1 C30.1 C45.1 C54.1 C56.1 J28.2 TP9.1 U1.8(VDD2) U3.8(VDD2) U5.8(VDD2)
AVCC: J28.1
DGND: C4.1 C12.1 C20.1 C27.2 C30.2 C45.2 C54.2 C56.2 U1.5(GND2) U3.5(GND2) U5.5(GND2)
GND_USH: C1.2 C31.1 FB1.1 R1.1 TP1.1 U1.4(GND1)
GND_VSH: C3.2 C33.1 FB3.1 R9.1 TP4.1 U3.4(GND1)
GND_WSH: C8.2 C38.1 FB5.1 R22.1 TP7.1 U5.4(GND1)
DOUTN_CH_U: J11.1 ; port DOUTN_CH_U
DOUTN_CH_U1: J11.2 R3.2 ; port DOUTN_CH_U1
DOUTN_CH_V: J19.1 ; port DOUTN_CH_V
DOUTN_CH_V1: J19.2 R12.2 ; port DOUTN_CH_V1
DOUTN_CH_W: J21.1 ; port DOUTN_CH_W
DOUTN_CH_W1: J21.2 R23.2 ; port DOUTN_CH_W1
DOUTP_CH_U: J10.1 ; port DOUTP_CH_U
DOUTP_CH_U1: J10.2 R5.2 ; port DOUTP_CH_U1
DOUTP_CH_V: J18.1 ; port DOUTP_CH_V
DOUTP_CH_V1: J18.2 R15.2 ; port DOUTP_CH_V1
DOUTP_CH_W: J20.1 ; port DOUTP_CH_W
DOUTP_CH_W1: J20.2 R25.2 ; port DOUTP_CH_W1
NetC2_1: C2.1 D47.3(C) R4.2 R39.1 U1.2(VINP)
NetC2_2: C2.2 D48.3(C) R2.2 U1.3(VINN)
NetC9_1: C9.1 D41.3(C) R14.2 R44.1 U3.2(VINP)
NetC9_2: C9.2 D42.3(C) R11.2 U3.3(VINN)
NetC18_1: C18.1 D35.3(C) R26.2 R47.1 U5.2(VINP)
NetC18_2: C18.2 D36.3(C) R24.2 U5.3(VINN)
NetFB1_2: FB1.2 R2.1
NetFB2_1: FB2.1 R1.2 TP2.1
NetFB2_2: FB2.2 R4.1
NetFB3_2: FB3.2 R11.1
NetFB4_1: FB4.1 R9.2 TP5.1
NetFB4_2: FB4.2 R14.1
NetFB5_2: FB5.2 R24.1
NetFB6_1: FB6.1 R22.2 TP8.1
NetFB6_2: FB6.2 R26.1
NetR3_1: R3.1 U1.6(VOUTN)
NetR5_1: R5.1 U1.7(VOUTP)
NetR12_1: R12.1 U3.6(VOUTN)
NetR15_1: R15.1 U3.7(VOUTP)
NetR23_1: R23.1 U5.6(VOUTN)
NetR25_1: R25.1 U5.7(VOUTP)

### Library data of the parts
C1 C3 C4 C8 C12 C20 = 06033C104JAT2A: as C52 on sheet Pg3-Microcontroller
C2 C9 C18 = 08055A331KAT2A: CAP, CERM, 330 pF, 50 V, +/- 10%, C0G/NP0, 0805; Manufacturer: AVX; Polarized: N; CompType: Capacitor; Value: 330pF; U/M: EA; Cap_F: 0.00000000033; Tolerance_%: 10; ESR_ohm: 0.189; Value1: 0.189 ohm; VDC_V: 50; Value2: 50V; TaMin_C: -55; TaMax_C: 125; Cap_Case: 0805
C27 = GMK325AB7106MM-T: CAP, CERM, 10uF, 35V, +/-20%, X7R, 1210; Manufacturer: Taiyo Yuden; Polarized: N; CompType: Capacitor; U/M: EA; Cap_F: 0.00001; Tolerance_%: 20; Value1: Unknown; VDC_V: 35; TaMin_C: -55; TaMax_C: 125
C30 = C0603C104K5RACTU: CAP, CERM, 0.1uF, 50V, +/-10%, X7R, 0603; Manufacturer: Kemet; Polarized: N; CompType: Capacitor; U/M: EA; Cap_F: 0.0000001; Tolerance_%: 10; Value1: Unknown; VDC_V: 50; TaMin_C: -55; TaMax_C: 125
C31 C33 C38 C45 C54 C56 = GRM188R71C105KA12D: as C35 on sheet Pg3-Microcontroller
D35 D36 D41 D42 D47 D48 = BAV99WT1G: Diode, P-N, 70V, 0.2A, SOT-323; Manufacturer: Diodes Inc
FB1-FB6 = MMZ1608B102C: as FB7 on sheet Pg3-Microcontroller
J10 J11 J18-J21 = 61300211121: Header, 2.54 mm, 2x1, Gold, TH; Manufacturer: Wurth Elektronik eiSos; SymbolCreator: a0412235; U/M: EA
J28 = 009155003301006: 3 pin berger; Manufacturer: FCI; SymbolCreator: a0799628; CompType: Connector; U/M: EA
R1 R9 R22 = WSLP39213L000FEB: RESISTOR, SMD, 0.003 OHM, 1%, 5W, 3921; Manufacturer: VISHAY DALE; SymbolCreator: x0199378
R2 R4 R11 R14 R24 R26 = RC0603FR-0712RL: RES, 12.0, 1%, 0.1 W, 0603; Manufacturer: Yageo America; CompType: Resistor; Value: 12.0; Res_ohm: 12; Value_Code: 12R0; Tolerance_%: 1; Power_W: 0.1; Value2: 0.1W; VDC_V: 150; TempCo: 200 ppm/C; U/M: EA
R3 R5 R12 R15 R23 R25 = CRCW060310R0FKEA: RES, 10.0 ohm, 1%, 0.1W, 0603; Manufacturer: Vishay-Dale; CompType: Resistor; Res_ohm: 10; Value_Code: 10R0; Tolerance_%: 1; Power_W: 0.1; VDC_V: 75; TempCo: 100 ppm/C; EIA_Code: E96; U/M: EA
R39 R44 R47 = CRCW0603160KFKEA: RES, 160 k, 1%, 0.1 W, 0603; Manufacturer: Vishay-Dale; CompType: Resistor; Value: 160k; Res_ohm: 160000; Tolerance_%: 1; Power_W: 0.1; Value2: 0.1W; VDC_V: 75; TempCo: 100 ppm/C; U/M: EA
TP1 TP2 TP4 TP5 TP7 TP8 = TP-5001-BLACK: Test Point,  Black, Thru Hole Color Keyed; Manufacturer: Keystone; PartNumber: 5001; area: 10.000; Value: 5001
TP9 = TP-040_RND: as TP11 on sheet Pg3-Microcontroller
U1 U3 U5 = AMC1100DUBR: Fully-Differential Isolation Amplifier, DUB0008A; Manufacturer: Texas Instruments; SymbolCreator: a0411947; CompType: IC; U/M: EA

## Sheet Pg5-Voltage signal condtioning.SchDoc: Analog Front End Opamp (Voltage)
size 431 x 279 mm; Date: Not shown in title block; ApprovedBy: Not shown in title block; CheckedBy: Not shown in title block; Author: Not shown in title block; CompanyName: Not shown in title block; Engineer: Not shown in title block; Organization: Not shown in title block; Address1: Not shown in title block; Address2: Not shown in title block; Address3: Not shown in title block; Address4: Not shown in title block; DocumentNumber: 4; Revision: Use project parameter SCH_Rev; SheetNumber: 5; SheetTotal: 9; PageSetup: Record=PageOptions¦CenterHorizontal=True¦CenterVertical=True¦PrintScale=1.00¦XCorrection=1.00¦YCorrection=1.00¦PrintKind=0¦BorderSize=5000000¦LeftOffset=0¦BottomOffset=0¦Orientation=2¦PaperLength=1000¦PaperWidth=1000¦Scale=100¦PaperSource=15¦PrintQuality=600¦MediaType=1¦DitherType=10¦PaperKind=Letter¦PrintScaleMode=1
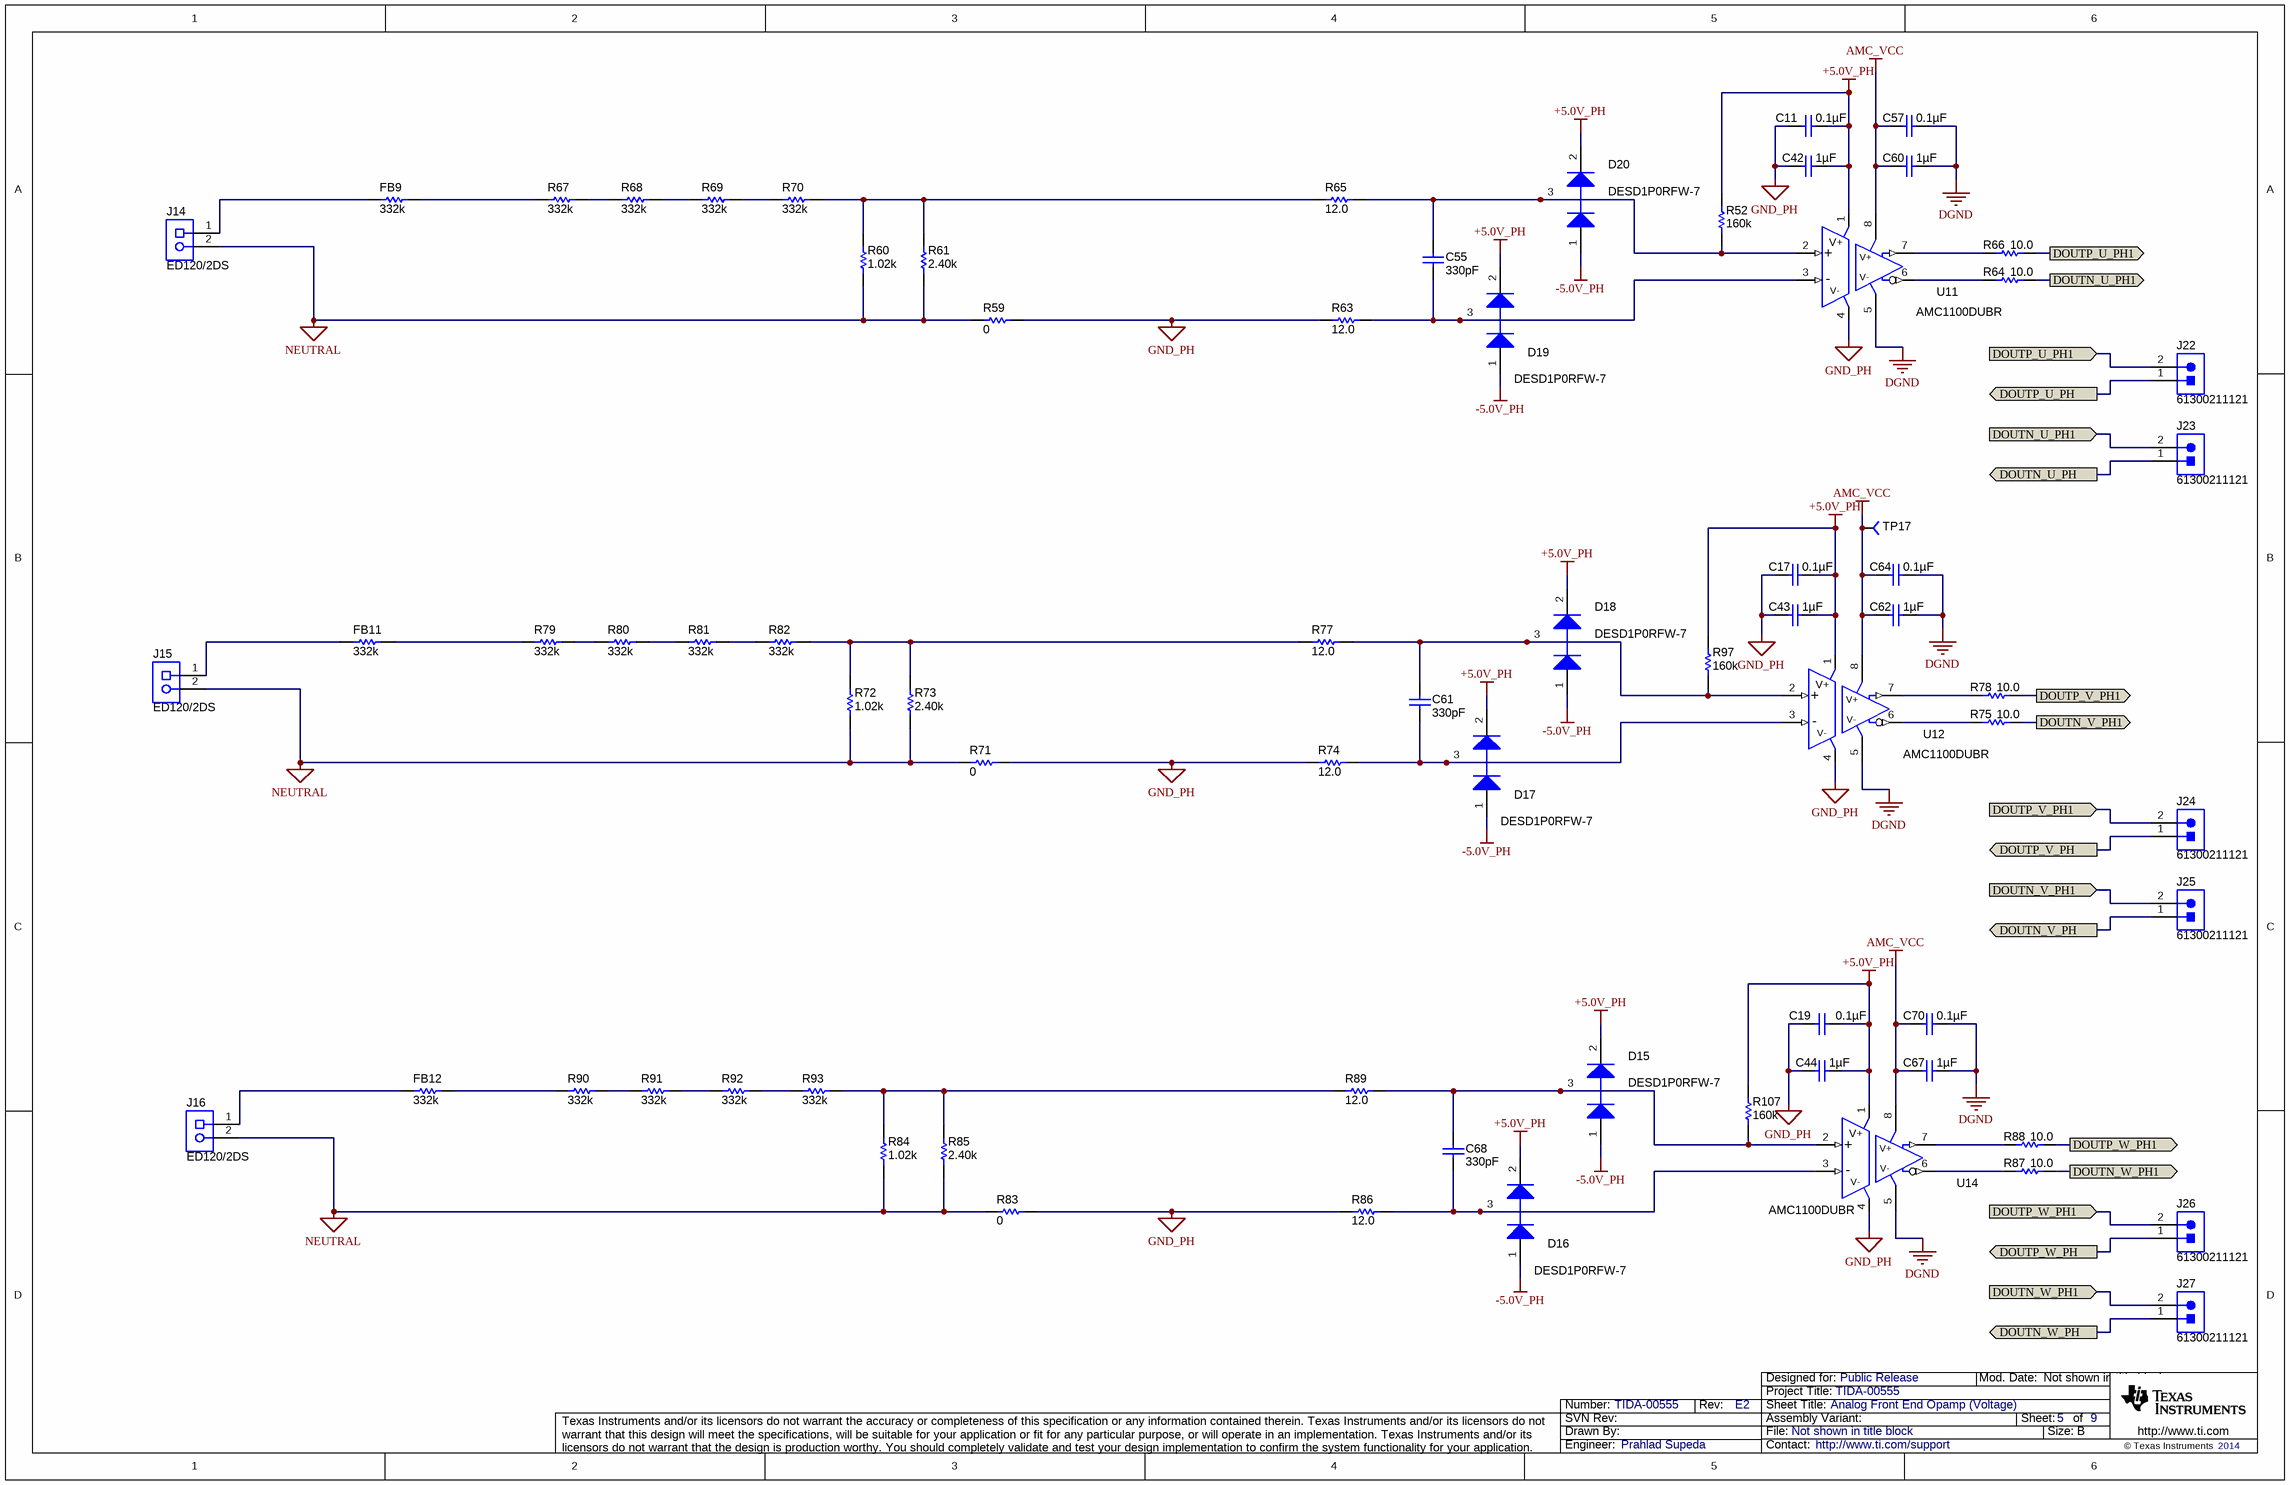
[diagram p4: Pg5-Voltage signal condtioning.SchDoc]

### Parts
C11  ValueDisplayed: 0.1µF  [0603]
C17  ValueDisplayed: 0.1µF  [0603]
C19  ValueDisplayed: 0.1µF  [0603]
C42  ValueDisplayed: 1µF  [0603]  (hidden comment: GRM188R71C105KA12D)
C43  ValueDisplayed: 1µF  [0603]  (hidden comment: GRM188R71C105KA12D)
C44  ValueDisplayed: 1µF  [0603]  (hidden comment: GRM188R71C105KA12D)
C55  ValueDisplayed: 330pF  [0805_HV]  (hidden comment: 08055A331KAT2A)
C57  ValueDisplayed: 0.1µF  [0603]
C60  ValueDisplayed: 1µF  [0603]  (hidden comment: GRM188R71C105KA12D)
C61  ValueDisplayed: 330pF  [0805_HV]  (hidden comment: 08055A331KAT2A)
C62  ValueDisplayed: 1µF  [0603]  (hidden comment: GRM188R71C105KA12D)
C64  ValueDisplayed: 0.1µF  [0603]
C67  ValueDisplayed: 1µF  [0603]  (hidden comment: GRM188R71C105KA12D)
C68  ValueDisplayed: 330pF  [0805_HV]  (hidden comment: 08055A331KAT2A)
C70  ValueDisplayed: 0.1µF  [0603]
D15  value DESD1P0RFW-7  [SOT-323]
D16  value DESD1P0RFW-7  [SOT-323]
D17  value DESD1P0RFW-7  [SOT-323]
D18  value DESD1P0RFW-7  [SOT-323]
D19  value DESD1P0RFW-7  [SOT-323]
D20  value DESD1P0RFW-7  [SOT-323]
FB9  ValueDisplayed: 332k  [1206]  (hidden comment: ERJ-8ENF3323V)
FB11  ValueDisplayed: 332k  [1206]  (hidden comment: ERJ-8ENF3323V)
FB12  ValueDisplayed: 332k  [1206]  (hidden comment: ERJ-8ENF3323V)
J14  ED120/2DS  [CONN_ED120-2DS]
J15  ED120/2DS  [CONN_ED120-2DS]
J16  ED120/2DS  [CONN_ED120-2DS]
J22  61300211121  [WURTH_61300211121]
J23  61300211121  [WURTH_61300211121]
J24  61300211121  [WURTH_61300211121]
J25  61300211121  [WURTH_61300211121]
J26  61300211121  [WURTH_61300211121]
J27  61300211121  [WURTH_61300211121]
R52  ValueDisplayed: 160k  [0603]  (hidden comment: CRCW0603160KFKEA)
R59  value 0  [0805_HV]  (hidden comment: CRCW08050000Z0EA)
R60  ValueDisplayed: 1.02k  [1206]  (hidden comment: RC1206FR-071K02L)
R61  ValueDisplayed: 2.40k  [1206]  (hidden comment: RC1206FR-072K4L)
R63  ValueDisplayed: 12.0  [0603]  (hidden comment: RC0603FR-0712RL)
R64  value 10.0  [0603]
R65  ValueDisplayed: 12.0  [0603]  (hidden comment: RC0603FR-0712RL)
R66  value 10.0  [0603]
R67  ValueDisplayed: 332k  [1206]  (hidden comment: ERJ-8ENF3323V)
R68  ValueDisplayed: 332k  [1206]  (hidden comment: ERJ-8ENF3323V)
R69  ValueDisplayed: 332k  [1206]  (hidden comment: ERJ-8ENF3323V)
R70  ValueDisplayed: 332k  [1206]  (hidden comment: ERJ-8ENF3323V)
R71  value 0  [0805_HV]  (hidden comment: CRCW08050000Z0EA)
R72  ValueDisplayed: 1.02k  [1206]  (hidden comment: RC1206FR-071K02L)
R73  ValueDisplayed: 2.40k  [1206]  (hidden comment: RC1206FR-072K4L)
R74  ValueDisplayed: 12.0  [0603]  (hidden comment: RC0603FR-0712RL)
R75  value 10.0  [0603]
R77  ValueDisplayed: 12.0  [0603]  (hidden comment: RC0603FR-0712RL)
R78  value 10.0  [0603]
R79  ValueDisplayed: 332k  [1206]  (hidden comment: ERJ-8ENF3323V)
R80  ValueDisplayed: 332k  [1206]  (hidden comment: ERJ-8ENF3323V)
R81  ValueDisplayed: 332k  [1206]  (hidden comment: ERJ-8ENF3323V)
R82  ValueDisplayed: 332k  [1206]  (hidden comment: ERJ-8ENF3323V)
R83  value 0  [0805_HV]  (hidden comment: CRCW08050000Z0EA)
R84  ValueDisplayed: 1.02k  [1206]  (hidden comment: RC1206FR-071K02L)
R85  ValueDisplayed: 2.40k  [1206]  (hidden comment: RC1206FR-072K4L)
R86  ValueDisplayed: 12.0  [0603]  (hidden comment: RC0603FR-0712RL)
R87  value 10.0  [0603]
R88  value 10.0  [0603]
R89  ValueDisplayed: 12.0  [0603]  (hidden comment: RC0603FR-0712RL)
R90  ValueDisplayed: 332k  [1206]  (hidden comment: ERJ-8ENF3323V)
R91  ValueDisplayed: 332k  [1206]  (hidden comment: ERJ-8ENF3323V)
R92  ValueDisplayed: 332k  [1206]  (hidden comment: ERJ-8ENF3323V)
R93  ValueDisplayed: 332k  [1206]  (hidden comment: ERJ-8ENF3323V)
R97  ValueDisplayed: 160k  [0603]  (hidden comment: CRCW0603160KFKEA)
R107  ValueDisplayed: 160k  [0603]  (hidden comment: CRCW0603160KFKEA)
TP17  (no value)  [TP-040_RND]
U11  AMC1100DUBR  [DUB0008A_N]
U12  AMC1100DUBR  [DUB0008A_N]
U14  AMC1100DUBR  [DUB0008A_N]

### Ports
DOUTN_U_PH1 (in), DOUTN_U_PH1 (out), DOUTN_U_PH (out), DOUTN_V_PH1 (in), DOUTN_V_PH1 (out), DOUTN_V_PH (out), DOUTN_W_PH1 (in), DOUTN_W_PH1 (out), DOUTN_W_PH (out), DOUTP_U_PH1 (in), DOUTP_U_PH1 (out), DOUTP_U_PH (out), DOUTP_V_PH1 (in), DOUTP_V_PH1 (out), DOUTP_V_PH (out), DOUTP_W_PH1 (in), DOUTP_W_PH1 (out), DOUTP_W_PH (out)

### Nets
+5.0V_PH: C11.1 C17.1 C19.1 C42.2 C43.2 C44.2 D15.2(K) D16.2(K) D17.2(K) D18.2(K) D19.2(K) D20.2(K) R52.2 R97.2 R107.2 U11.1(VDD1) U12.1(VDD1) U14.1(VDD1)
-5.0V_PH: D15.1(A) D16.1(A) D17.1(A) D18.1(A) D19.1(A) D20.1(A)
AMC_VCC: C57.2 C60.1 C62.1 C64.2 C67.1 C70.2 TP17.1 U11.8(VDD2) U12.8(VDD2) U14.8(VDD2)
DGND: C57.1 C60.2 C62.2 C64.1 C67.2 C70.1 U11.5(GND2) U12.5(GND2) U14.5(GND2)
GND_PH: C11.2 C17.2 C19.2 C42.1 C43.1 C44.1 R59.2 R63.1 R71.2 R74.1 R83.2 R86.1 U11.4(GND1) U12.4(GND1) U14.4(GND1)
NEUTRAL: J14.2 J15.2 J16.2 R59.1 R60.1 R61.1 R71.1 R72.1 R73.1 R83.1 R84.1 R85.1
DOUTN_U_PH: J23.1 ; port DOUTN_U_PH
DOUTN_U_PH1: J23.2 R64.2 ; port DOUTN_U_PH1
DOUTN_V_PH: J25.1 ; port DOUTN_V_PH
DOUTN_V_PH1: J25.2 R75.2 ; port DOUTN_V_PH1
DOUTN_W_PH: J27.1 ; port DOUTN_W_PH
DOUTN_W_PH1: J27.2 R87.2 ; port DOUTN_W_PH1
DOUTP_U_PH: J22.1 ; port DOUTP_U_PH
DOUTP_U_PH1: J22.2 R66.2 ; port DOUTP_U_PH1
DOUTP_V_PH: J24.1 ; port DOUTP_V_PH
DOUTP_V_PH1: J24.2 R78.2 ; port DOUTP_V_PH1
DOUTP_W_PH: J26.1 ; port DOUTP_W_PH
DOUTP_W_PH1: J26.2 R88.2 ; port DOUTP_W_PH1
NetC55_1: C55.1 D20.3(C) R52.1 R65.2 U11.2(VINP)
NetC55_2: C55.2 D19.3(C) R63.2 U11.3(VINN)
NetC61_1: C61.1 D18.3(C) R77.2 R97.1 U12.2(VINP)
NetC61_2: C61.2 D17.3(C) R74.2 U12.3(VINN)
NetC68_1: C68.1 D15.3(C) R89.2 R107.1 U14.2(VINP)
NetC68_2: C68.2 D16.3(C) R86.2 U14.3(VINN)
NetFB9_1: FB9.1 J14.1
NetFB9_2: FB9.2 R67.1
NetFB11_1: FB11.1 J15.1
NetFB11_2: FB11.2 R79.1
NetFB12_1: FB12.1 J16.1
NetFB12_2: FB12.2 R90.1
NetR60_2: R60.2 R61.2 R65.1 R70.2
NetR64_1: R64.1 U11.6(VOUTN)
NetR66_1: R66.1 U11.7(VOUTP)
NetR67_2: R67.2 R68.1
NetR68_2: R68.2 R69.1
NetR69_2: R69.2 R70.1
NetR72_2: R72.2 R73.2 R77.1 R82.2
NetR75_1: R75.1 U12.6(VOUTN)
NetR78_1: R78.1 U12.7(VOUTP)
NetR79_2: R79.2 R80.1
NetR80_2: R80.2 R81.1
NetR81_2: R81.2 R82.1
NetR84_2: R84.2 R85.2 R89.1 R93.2
NetR87_1: R87.1 U14.6(VOUTN)
NetR88_1: R88.1 U14.7(VOUTP)
NetR90_2: R90.2 R91.1
NetR91_2: R91.2 R92.1
NetR92_2: R92.2 R93.1

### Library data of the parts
C11 C17 C19 C57 C64 C70 = 06033C104JAT2A: as C52 on sheet Pg3-Microcontroller
C42-C44 C60 C62 C67 = GRM188R71C105KA12D: as C35 on sheet Pg3-Microcontroller
C55 C61 C68 = 08055A331KAT2A: as C2 on sheet Pg4-Current  signal condtioning
D15-D20 = BAV99WT1G: as D35 on sheet Pg4-Current  signal condtioning
FB9 FB11 FB12 R67-R70 R79-R82 R90-R93 = ERJ-8ENF3323V: RES, 332 k, 1%, 0.25 W, 1206; Manufacturer: Panasonic; CompType: Resistor; Value: 332k; Res_ohm: 332000; Tolerance_%: 1; Power_W: 0.25; Value2: 0.25W; VDC_V: 200; TempCo: 100 ppm/C; EIA_Code: E96; U/M: EA
J14-J16 = ED120/2DS: TERMINAL BLOCK 5.08MM VERT 2POS, TH; Manufacturer: On-Shore Technology; SymbolCreator: a0412235; U/M: EA
J22-J27 = 61300211121: as J10 on sheet Pg4-Current  signal condtioning
R52 R97 R107 = CRCW0603160KFKEA: as R39 on sheet Pg4-Current  signal condtioning
R59 R71 R83 = CRCW08050000Z0EA: RES, 0 ohm, 5%, 0.125W, 0805; Manufacturer: Vishay-Dale; CompType: Resistor; Value_Code: 0000; Tolerance_%: 5; Power_W: 0.125; VDC_V: 150; TempCo: 200 ppm/C; EIA_Code: E24; U/M: EA
R60 R72 R84 = RC1206FR-072K4L: RES SMD 1.02K OHM 1% 1/4W 1206; Manufacturer: Yageo America; CompType: Resistor; Res_ohm: 2400; Value_Code: 1K02; Tolerance_%: 1; Power_W: 0.25; Value2: 0.25W; VDC_V: 200; TempCo: 100 ppm/C; U/M: EA
R61 R73 R85 = RC1206FR-072K4L: RES, 2.40 k, 1%, 0.25 W, 1206; Manufacturer: Yageo America; CompType: Resistor; Value: 2.40k; Res_ohm: 2400; Value_Code: 2k40; Tolerance_%: 1; Power_W: 0.25; Value2: 0.25W; VDC_V: 200; TempCo: 100 ppm/C; U/M: EA
R63 R65 R74 R77 R86 R89 = RC0603FR-0712RL: as R2 on sheet Pg4-Current  signal condtioning
R64 R66 R75 R78 R87 R88 = CRCW060310R0FKEA: as R3 on sheet Pg4-Current  signal condtioning
TP17 = TP-040_RND: as TP11 on sheet Pg3-Microcontroller
U11 U12 U14 = AMC1100DUBR: as U1 on sheet Pg4-Current  signal condtioning

## Sheet Pg6-Power supply 1.SchDoc: Isolated Poser Supply 2
size 431 x 279 mm; Date: Not shown in title block; ApprovedBy: Not shown in title block; CheckedBy: Not shown in title block; Author: Not shown in title block; CompanyName: Not shown in title block; Engineer: Not shown in title block; Organization: Not shown in title block; Address1: Not shown in title block; Address2: Not shown in title block; Address3: Not shown in title block; Address4: Not shown in title block; DocumentNumber: 6; Revision: Use project parameter SCH_Rev; SheetNumber: 6; SheetTotal: 9; PageSetup: Record=PageOptions¦CenterHorizontal=True¦CenterVertical=True¦PrintScale=1.00¦XCorrection=1.00¦YCorrection=1.00¦PrintKind=0¦BorderSize=5000000¦LeftOffset=0¦BottomOffset=0¦Orientation=2¦PaperLength=1000¦PaperWidth=1000¦Scale=100¦PaperSource=15¦PrintQuality=600¦MediaType=1¦DitherType=10¦PaperKind=Letter¦PrintScaleMode=1
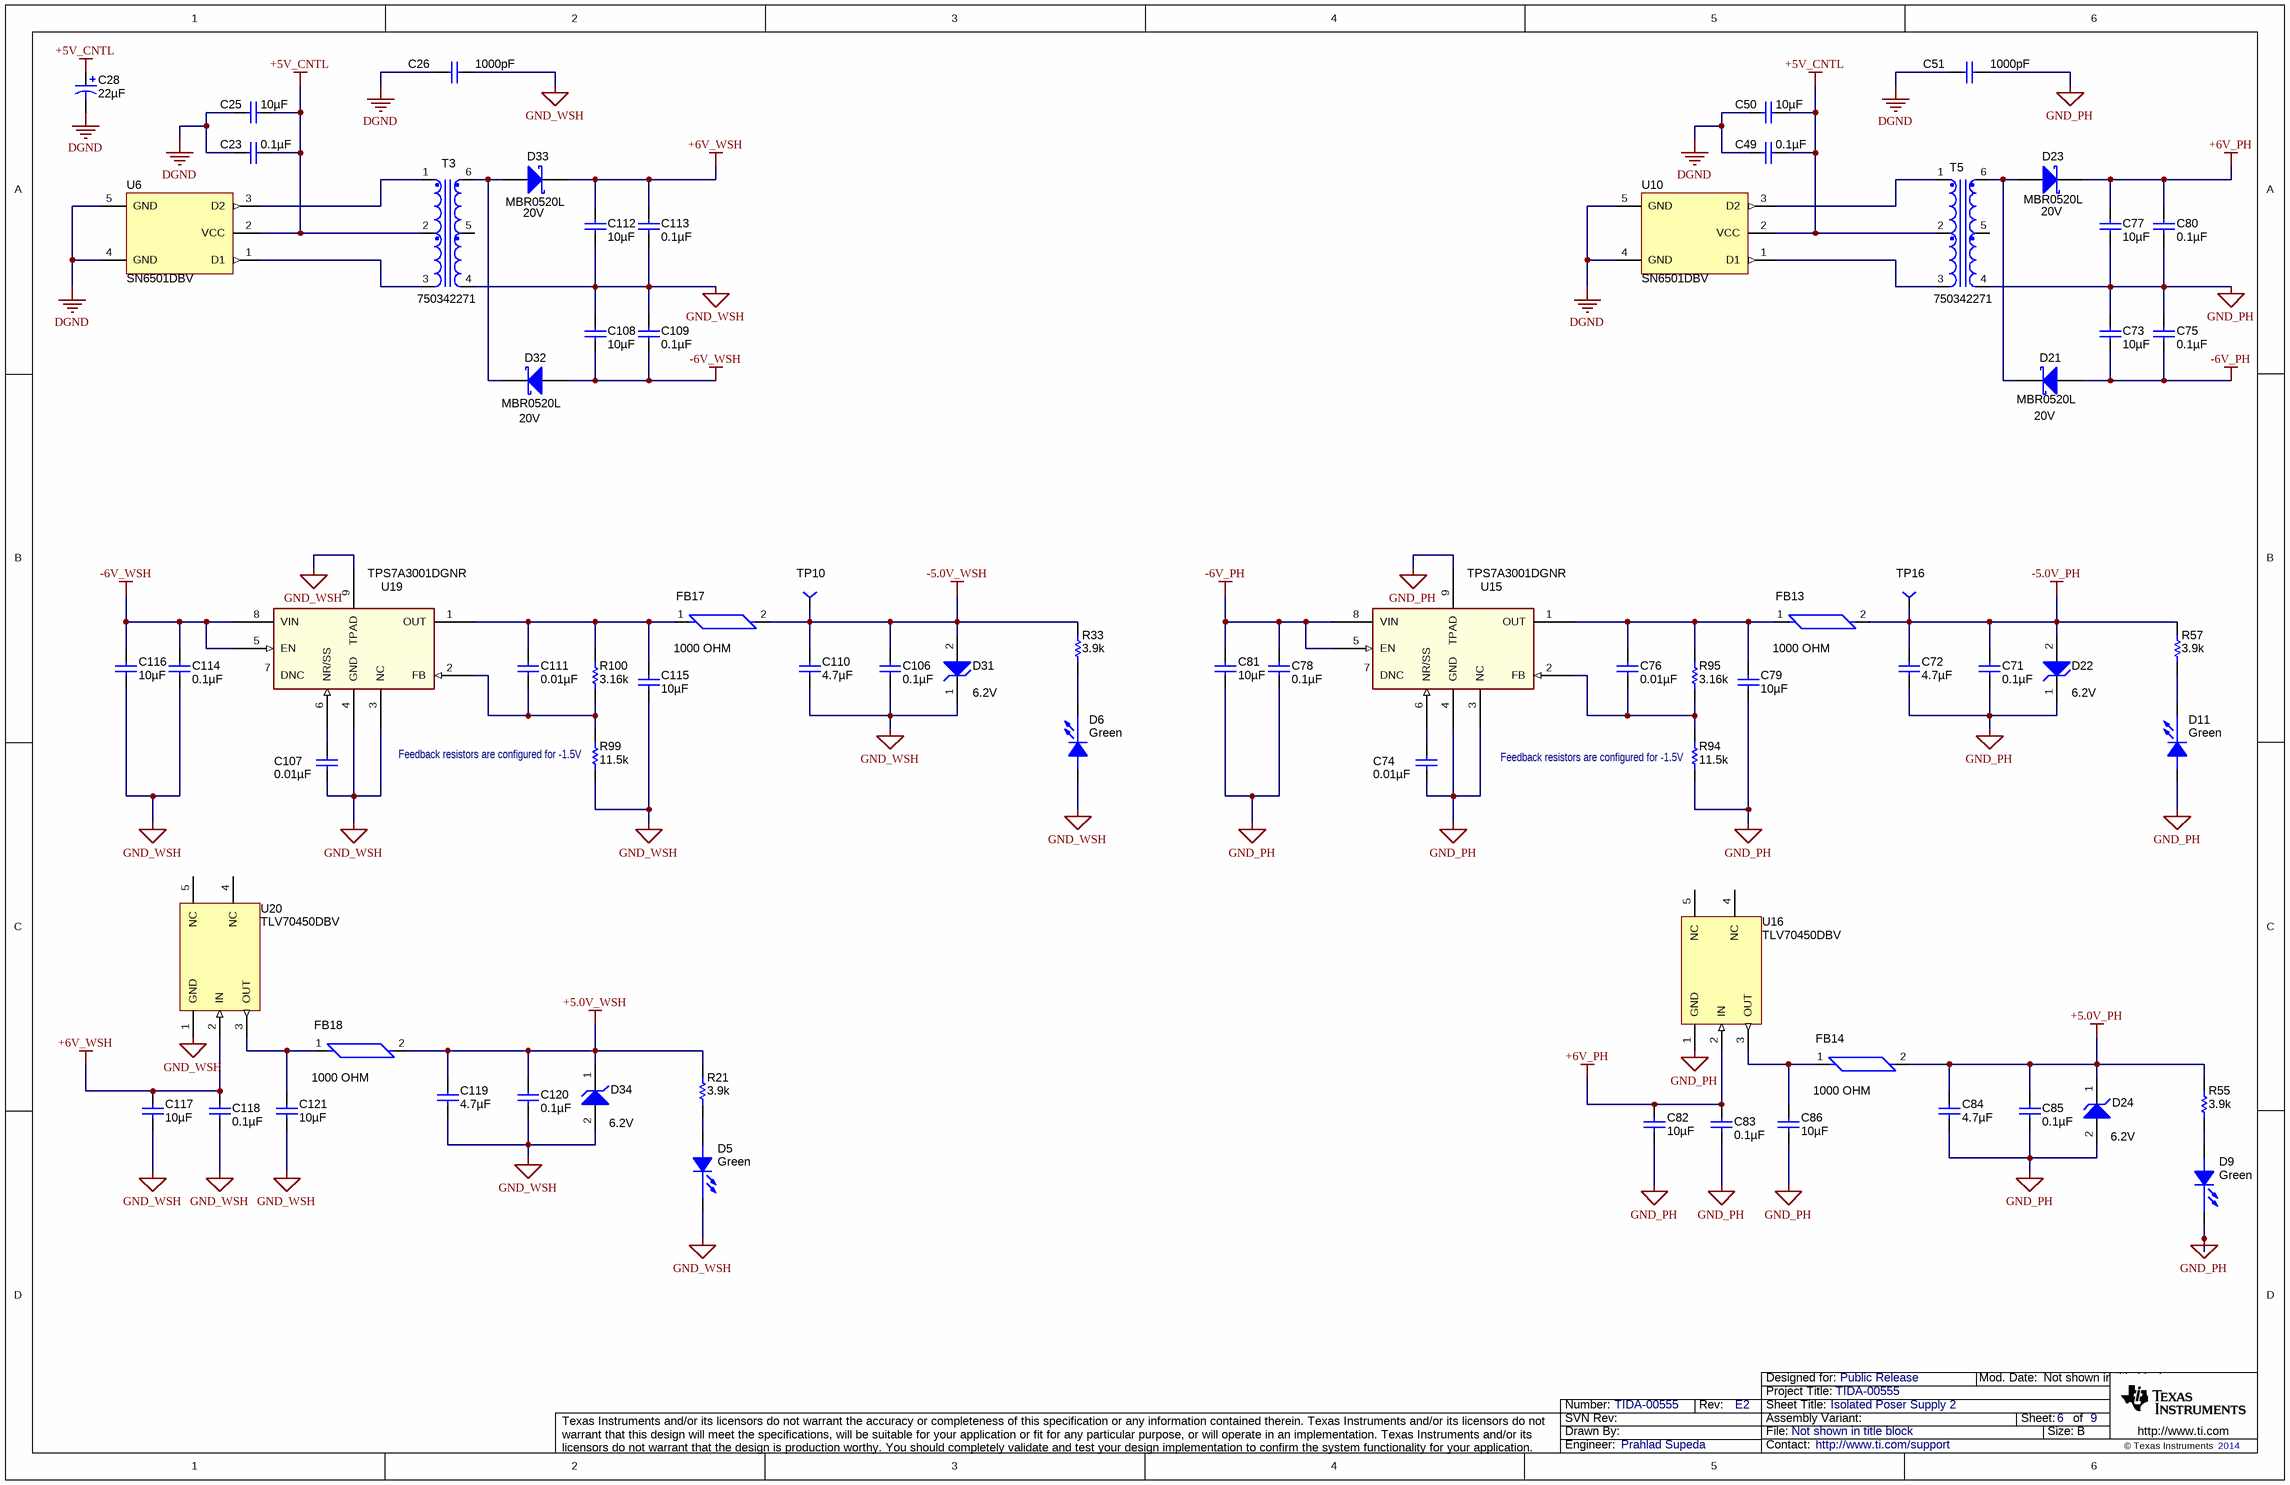
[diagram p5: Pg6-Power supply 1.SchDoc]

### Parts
C23  ValueDisplayed: 0.1µF  [0603]
C25  ValueDisplayed: 10µF  [1210]
C26  value 1000pF  [CAP_200mil]
C28  ValueDisplayed: 22µF  [SM_RADIAL_5MM]  (hidden comment: UUD1E220MCL1GS)
C49  ValueDisplayed: 0.1µF  [0603]
C50  ValueDisplayed: 10µF  [1210]
C51  value 1000pF  [CAP_200mil]
C71  ValueDisplayed: 0.1µF  [0603]
C72  ValueDisplayed: 4.7µF  [0805_HV]
C73  ValueDisplayed: 10µF  [1210]
C74  ValueDisplayed: 0.01µF  [0603]
C75  ValueDisplayed: 0.1µF  [0603]
C76  ValueDisplayed: 0.01µF  [0603]
C77  ValueDisplayed: 10µF  [1210]
C78  ValueDisplayed: 0.1µF  [0603]
C79  ValueDisplayed: 10µF  [1210]
C80  ValueDisplayed: 0.1µF  [0603]
C81  ValueDisplayed: 10µF  [1210]
C82  ValueDisplayed: 10µF  [1210]
C83  ValueDisplayed: 0.1µF  [0603]
C84  ValueDisplayed: 4.7µF  [0805_HV]
C85  ValueDisplayed: 0.1µF  [0603]
C86  ValueDisplayed: 10µF  [1210]
C106  ValueDisplayed: 0.1µF  [0603]
C107  ValueDisplayed: 0.01µF  [0603]
C108  ValueDisplayed: 10µF  [1210]
C109  ValueDisplayed: 0.1µF  [0603]
C110  ValueDisplayed: 4.7µF  [0805_HV]
C111  ValueDisplayed: 0.01µF  [0603]
C112  ValueDisplayed: 10µF  [1210]
C113  ValueDisplayed: 0.1µF  [0603]
C114  ValueDisplayed: 0.1µF  [0603]
C115  ValueDisplayed: 10µF  [1210]
C116  ValueDisplayed: 10µF  [1210]
C117  ValueDisplayed: 10µF  [1210]
C118  ValueDisplayed: 0.1µF  [0603]
C119  ValueDisplayed: 4.7µF  [0805_HV]
C120  ValueDisplayed: 0.1µF  [0603]
C121  ValueDisplayed: 10µF  [1210]
D5  value Green  [LED0603AA]
D6  value Green  [LED0603AA]
D9  value Green  [LED0603AA]
D11  value Green  [LED0603AA]
D21  MBR0520L  value 20V  [SOD-123]
D22  value 6.2V  [powerDI123]
D23  MBR0520L  value 20V  [SOD-123]
D24  value 6.2V  [powerDI123]
D31  value 6.2V  [powerDI123]
D32  MBR0520L  value 20V  [SOD-123]
D33  MBR0520L  value 20V  [SOD-123]
D34  value 6.2V  [powerDI123]
FB13  value 1000 OHM  [FB0603]
FB14  value 1000 OHM  [FB0603]
FB17  value 1000 OHM  [FB0603]
FB18  value 1000 OHM  [FB0603]
R21  value 3.9k  [0603]
R33  value 3.9k  [0603]
R55  value 3.9k  [0603]
R57  value 3.9k  [0603]
R94  value 11.5k  [0603]
R95  ValueDisplayed: 3.16k  [0603]  (hidden comment: RC0603FR-073K16L)
R99  value 11.5k  [0603]
R100  ValueDisplayed: 3.16k  [0603]  (hidden comment: RC0603FR-073K16L)
T3  750342271  [760390015]
T5  750342271  [760390015]
TP10  (no value)  [TP-040_RND]
TP16  (no value)  [TP-040_RND]
U6  SN6501DBV  [DBV0005A_N]
U10  SN6501DBV  [DBV0005A_N]
U15  (no value)  [MSOP8(DGN)]
U16  TLV70450DBV  [DBV0005A_N]
U19  (no value)  [MSOP8(DGN)]
U20  TLV70450DBV  [DBV0005A_N]

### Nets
+5.0V_PH: C84.2 C85.1 D24.1(K) FB14.2 R55.2
+5.0V_WSH: C119.2 C120.1 D34.1(K) FB18.2 R21.2
+5V_CNTL: C23.2 C25.2 C28.1(+) C49.2 C50.2 T3.2 T5.2 U6.2(VCC) U10.2(VCC)
+6V_PH: C77.1 C80.1 C82.2 C83.1 D23.1(K) U16.2(IN)
+6V_WSH: C112.1 C113.1 C117.2 C118.1 D33.1(K) U20.2(IN)
-5.0V_PH: C71.1 C72.2 D22.2(A) FB13.2 R57.2 TP16.1
-5.0V_WSH: C106.1 C110.2 D31.2(A) FB17.2 R33.2 TP10.1
-6V_PH: C73.2 C75.2 C78.1 C81.2 D21.2(A) U15.5(EN) U15.8(VIN)
-6V_WSH: C108.2 C109.2 C114.1 C116.2 D32.2(A) U19.5(EN) U19.8(VIN)
DGND: C23.1 C25.1 C26.1 C28.2(-) C49.1 C50.1 C51.1 U6.4(GND) U6.5(GND) U10.4(GND) U10.5(GND)
GND_PH: C51.2 C71.2 C72.1 C73.1 C74.1 C75.1 C77.2 C78.2 C79.1 C80.2 C81.1 C82.1 C83.2 C84.1 C85.2 C86.1 D9.1(C) D11.2(A) D22.1(K) D24.2(A) R94.1 T5.4 U15.3(NC) U15.4(GND) U15.9(TPAD) U16.1(GND)
GND_WSH: C26.2 C106.2 C107.1 C108.1 C109.1 C110.1 C112.2 C113.2 C114.2 C115.1 C116.1 C117.1 C118.2 C119.1 C120.2 C121.1 D5.1(C) D6.2(A) D31.1(K) D34.2(A) R99.1 T3.4 U19.3(NC) U19.4(GND) U19.9(TPAD) U20.1(GND)
NetC74_2: C74.2 U15.6(NR/SS)
NetC76_1: C76.1 C79.2 FB13.1 R95.2 U15.1(OUT)
NetC76_2: C76.2 R94.2 R95.1 U15.2(FB)
NetC86_2: C86.2 FB14.1 U16.3(OUT)
NetC107_2: C107.2 U19.6(NR/SS)
NetC111_1: C111.1 R99.2 R100.1 U19.2(FB)
NetC111_2: C111.2 C115.2 FB17.1 R100.2 U19.1(OUT)
NetC121_2: C121.2 FB18.1 U20.3(OUT)
NetD5_2: D5.2(A) R21.1
NetD6_1: D6.1(C) R33.1
NetD9_2: D9.2(A) R55.1
NetD11_1: D11.1(C) R57.1
NetD21_1: D21.1(K) D23.2(A) T5.6
NetD32_1: D32.1(K) D33.2(A) T3.6
NetT3_1: T3.1 U6.3(D2)
NetT3_3: T3.3 U6.1(D1)
NetT5_1: T5.1 U10.3(D2)
NetT5_3: T5.3 U10.1(D1)

Not connected (* = marked no-connect by the designer): T3 5; T5 5; U15 7(DNC); U16 4(NC) 5(NC); U19 7(DNC); U20 4(NC) 5(NC)

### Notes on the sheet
- (near R99) Feedback resistors are configured for -1.5V
- (near R94) Feedback resistors are configured for -1.5V

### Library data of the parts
C23 C49 C71 C75 C78 C80 C83 C85 C106 C109 C113 C114 C118 C120 = C0603C104K5RACTU: as C30 on sheet Pg4-Current  signal condtioning
C25 C50 C73 C77 C79 C81 C82 C86 C108 C112 C115-C117 C121 = GMK325AB7106MM-T: as C27 on sheet Pg4-Current  signal condtioning
C26 C51 = 202R18W102KV4E: CAP CER 1000PF 1KV 10% RADIAL; PartNumber: S102K29Y5PN63J5R; Manufacturer: Vishay BC Components; Polarized: N; CompType: Capacitor; Tolerance_%: 0
C28 = UUD1E220MCL1GS: CAP, AL, 22uF, 25V, +/-20%, 0.76 ohm, SMD; Manufacturer: Nichicon; Polarized: Y; CompType: Capacitor; U/M: EA; Cap_F: 0.000022; Tolerance_%: 20; VDC_V: 25; ESR_Ohm: 0.76; IRMS_A: 0.15; TaMin_C: -55; TaMax_C: 105; Cap_Case: 5x5.8
C72 C84 C110 C119 = C2012X5R1H475K125AB: CAP, CERM, 4.7uF, 50V, +/-10%, X5R, 0805; Manufacturer: TDK; Polarized: N; CompType: Capacitor; U/M: EA; Cap_F: 0.0000047; Tolerance_%: 10; Value1: Unknown; VDC_V: 50; TaMin_C: -55; TaMax_C: 85; Cap_Case: 0805
C74 C76 C107 C111 = 06031C103JAT2A: CAP, CERM, 0.01uF, 100V, +/-5%, X7R, 0603; Manufacturer: AVX; Polarized: N; CompType: Capacitor; U/M: EA; Cap_F: 0.00000001; Tolerance_%: 5; ESR_Ohm: 0.098; Value1: 0.098 ohm; VDC_V: 100; TaMin_C: -55; TaMax_C: 125
D5 D6 D9 D11 = LED_LG L29K-G2J1-24-Z: LED SmartLED Green 570NM; Manufacturer: OSRAM; SymbolCreator: x0120606
D21 D23 D32 D33 = MBR0520LT1G: Diode, Schottky, 20V, 0.5A, SOD-123; Manufacturer: Fairchild Semiconductor; U/M: EA; Vf_V: 0.385; Value2: 0.385V; Io_A: 0.5; Vr_V: 20; TJmax_C: 125; RJC_CperW: 150
D22 D24 D31 D34 = DFLZ6V2-7: Diode, Zener, 6.2V, 1W, PowerDI123; Manufacturer: Diodes Inc.; U/M: EA; Power_W: 1; Vz_V: 6.2; RJA_CperW: 110
FB13 FB14 FB17 FB18 = MMZ1608B102C: as FB7 on sheet Pg3-Microcontroller
R21 R33 R55 R57 = CRCW06033K90JNEA: RES, 3.9k ohm, 5%, 0.1W, 0603; Manufacturer: Vishay-Dale; CompType: Resistor; Res_ohm: 3900; Value_Code: 3k90; Tolerance_%: 5; Power_W: 0.1; VDC_V: 75; TempCo: 200 ppm/C; EIA_Code: E24; U/M: EA
R94 R99 = CRCW060311K5FKEA: RES, 11.5k ohm, 1%, 0.1W, 0603; Manufacturer: Vishay-Dale; CompType: Resistor; Res_ohm: 11500; Value_Code: 11k5; Tolerance_%: 1; Power_W: 0.1; VDC_V: 75; TempCo: 100 ppm/C; EIA_Code: E96; U/M: EA
R95 R100 = RC0603FR-073K16L: RES, 3.16 k, 1%, 0.1 W, 0603; Manufacturer: Yageo America; CompType: Resistor; Value: 3.16k; Res_ohm: 3160; Value_Code: 3k16; Tolerance_%: 1; Power_W: 0.1; Value2: 0.1W; VDC_V: 150; TempCo: 200 ppm/C; EIA_Code: E96; U/M: EA
T3 T5 = TRNSFMR: Transformer 469uH SMD; Manufacturer: Wurth Electronics Midcom
TP10 TP16 = TP-040_RND: as TP11 on sheet Pg3-Microcontroller
U6 U10 = SN6501DBV: Transformer Driver for Isolated Power Supplies, DBV0005A; Alternate Manufacturer: None; Manufacturer: Texas Instruments; SymbolCreator: a0411947; CompType: IC; U/M: EA
U15 U19 = TPS7A3001DGNR: -36V, -200mA, Ultralow-Noise, Negative Linear Regulator; Alternate Manufacturer: None; Manufacturer: Texas Instruments; CompType: IC; SymbolCreator: x0120606
U16 U20 = TLV70450DBV: Regulator, LDO, 5V, 0.15A, SOT23-5; Alternate Manufacturer: None; Manufacturer: Texas Instruments; SymbolCreator: x0120606; CompType: IC

## Sheet Pg7-Power supply 2.SchDoc: Isolated Poser Supply 1
size 431 x 279 mm; Date: Not shown in title block; ApprovedBy: Not shown in title block; CheckedBy: Not shown in title block; Author: Not shown in title block; CompanyName: Not shown in title block; Engineer: Not shown in title block; Organization: Not shown in title block; Address1: Not shown in title block; Address2: Not shown in title block; Address3: Not shown in title block; Address4: Not shown in title block; DocumentNumber: 5; Revision: Use project parameter SCH_Rev; SheetNumber: 7; SheetTotal: 9; PageSetup: Record=PageOptions¦CenterHorizontal=True¦CenterVertical=True¦PrintScale=0.62¦XCorrection=1.00¦YCorrection=1.00¦PrintKind=0¦BorderSize=5000000¦LeftOffset=0¦BottomOffset=0¦Orientation=2¦PaperLength=1000¦PaperWidth=1000¦Scale=100¦PaperSource=15¦PrintQuality=600¦MediaType=1¦DitherType=10¦PaperKind=Letter¦PrintScaleMode=1
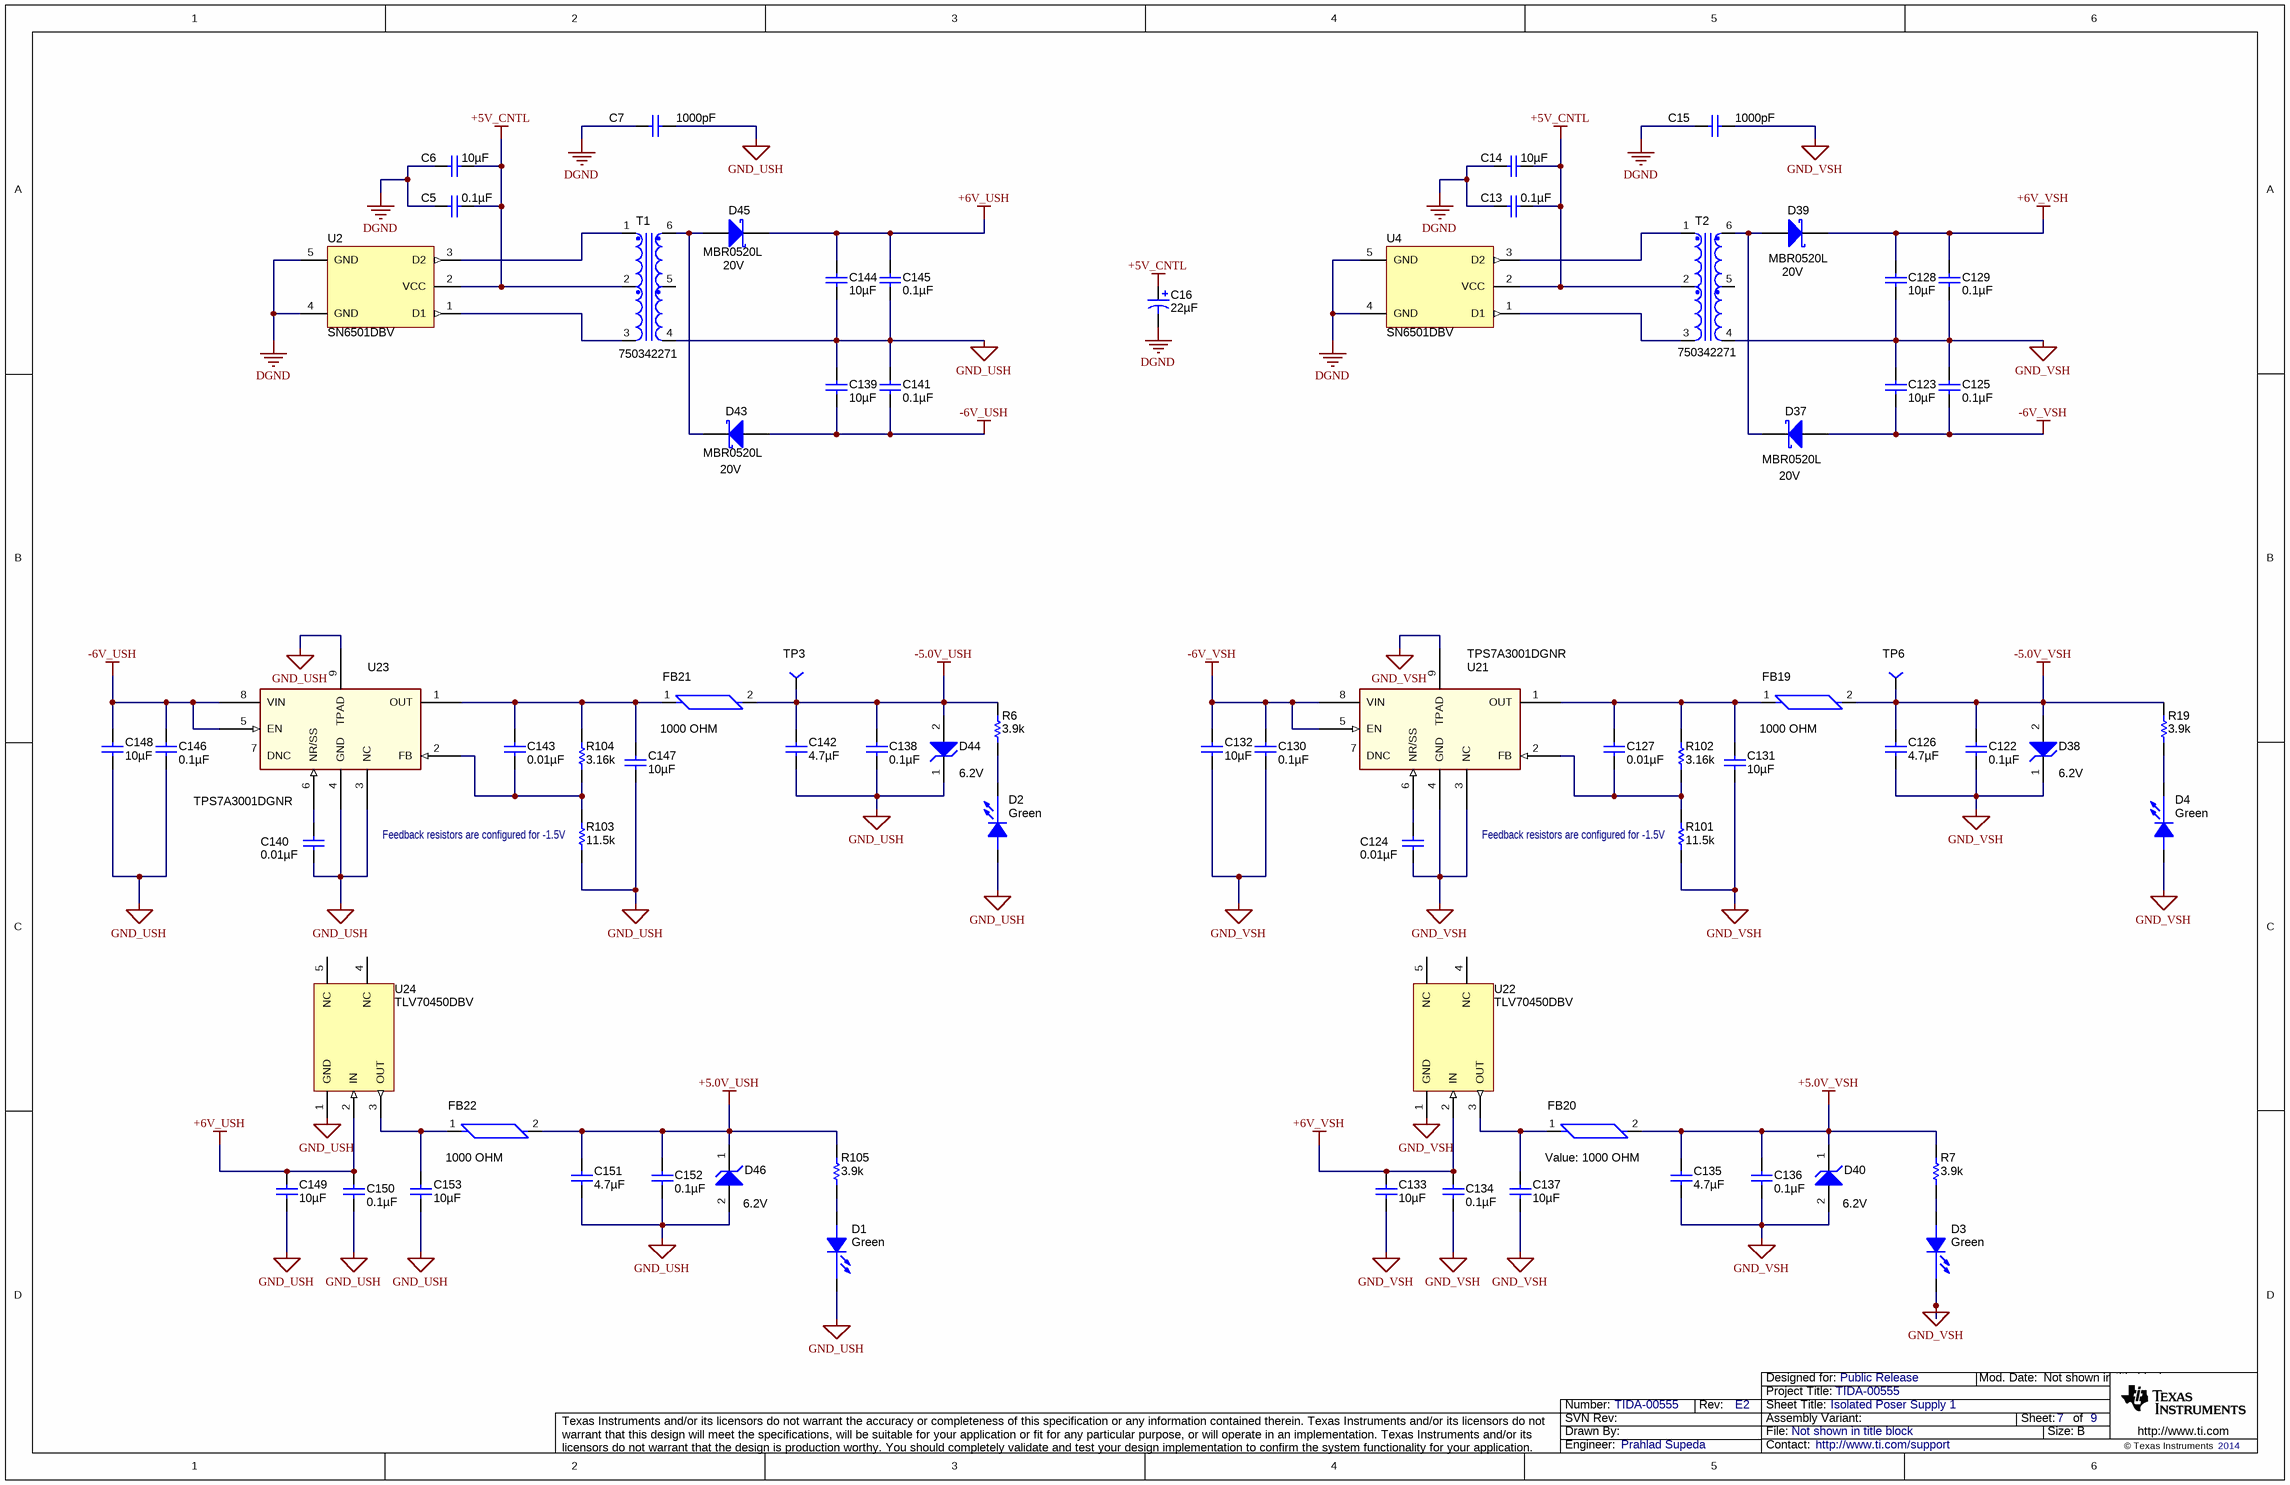
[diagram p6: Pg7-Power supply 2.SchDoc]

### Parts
C5  ValueDisplayed: 0.1µF  [0603]
C6  ValueDisplayed: 10µF  [1210]
C7  value 1000pF  [CAP_200mil]
C13  ValueDisplayed: 0.1µF  [0603]
C14  ValueDisplayed: 10µF  [1210]
C15  value 1000pF  [CAP_200mil]
C16  ValueDisplayed: 22µF  [SM_RADIAL_5MM]  (hidden comment: UUD1E220MCL1GS)
C122  ValueDisplayed: 0.1µF  [0603]
C123  ValueDisplayed: 10µF  [1210]
C124  ValueDisplayed: 0.01µF  [0603]
C125  ValueDisplayed: 0.1µF  [0603]
C126  ValueDisplayed: 4.7µF  [0805_HV]
C127  ValueDisplayed: 0.01µF  [0603]
C128  ValueDisplayed: 10µF  [1210]
C129  ValueDisplayed: 0.1µF  [0603]
C130  ValueDisplayed: 0.1µF  [0603]
C131  ValueDisplayed: 10µF  [1210]
C132  ValueDisplayed: 10µF  [1210]
C133  ValueDisplayed: 10µF  [1210]
C134  ValueDisplayed: 0.1µF  [0603]
C135  ValueDisplayed: 4.7µF  [0805_HV]
C136  ValueDisplayed: 0.1µF  [0603]
C137  ValueDisplayed: 10µF  [1210]
C138  ValueDisplayed: 0.1µF  [0603]
C139  ValueDisplayed: 10µF  [1210]
C140  ValueDisplayed: 0.01µF  [0603]
C141  ValueDisplayed: 0.1µF  [0603]
C142  ValueDisplayed: 4.7µF  [0805_HV]
C143  ValueDisplayed: 0.01µF  [0603]
C144  ValueDisplayed: 10µF  [1210]
C145  ValueDisplayed: 0.1µF  [0603]
C146  ValueDisplayed: 0.1µF  [0603]
C147  ValueDisplayed: 10µF  [1210]
C148  ValueDisplayed: 10µF  [1210]
C149  ValueDisplayed: 10µF  [1210]
C150  ValueDisplayed: 0.1µF  [0603]
C151  ValueDisplayed: 4.7µF  [0805_HV]
C152  ValueDisplayed: 0.1µF  [0603]
C153  ValueDisplayed: 10µF  [1210]
D1  value Green  [LED0603AA]
D2  value Green  [LED0603AA]
D3  value Green  [LED0603AA]
D4  value Green  [LED0603AA]
D37  MBR0520L  value 20V  [SOD-123]
D38  value 6.2V  [powerDI123]
D39  MBR0520L  value 20V  [SOD-123]
D40  value 6.2V  [powerDI123]
D43  MBR0520L  value 20V  [SOD-123]
D44  value 6.2V  [powerDI123]
D45  MBR0520L  value 20V  [SOD-123]
D46  value 6.2V  [powerDI123]
FB19  value 1000 OHM  [FB0603]
FB20  value 1000 OHM  [FB0603]
FB21  value 1000 OHM  [FB0603]
FB22  value 1000 OHM  [FB0603]
R6  value 3.9k  [0603]
R7  value 3.9k  [0603]
R19  value 3.9k  [0603]
R101  value 11.5k  [0603]
R102  ValueDisplayed: 3.16k  [0603]  (hidden comment: RC0603FR-073K16L)
R103  value 11.5k  [0603]
R104  ValueDisplayed: 3.16k  [0603]  (hidden comment: RC0603FR-073K16L)
R105  value 3.9k  [0603]
T1  750342271  [760390015]
T2  750342271  [760390015]
TP3  (no value)  [TP-040_RND]
TP6  (no value)  [TP-040_RND]
U2  SN6501DBV  [DBV0005A_N]
U4  SN6501DBV  [DBV0005A_N]
U21  (no value)  [MSOP8(DGN)]
U22  TLV70450DBV  [DBV0005A_N]
U23  TPS7A3001DGNR  [MSOP8(DGN)]
U24  TLV70450DBV  [DBV0005A_N]

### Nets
+5.0V_USH: C151.2 C152.1 D46.1(K) FB22.2 R105.2
+5.0V_VSH: C135.2 C136.1 D40.1(K) FB20.2 R7.2
+5V_CNTL: C5.2 C6.2 C13.2 C14.2 C16.1(+) T1.2 T2.2 U2.2(VCC) U4.2(VCC)
+6V_USH: C144.1 C145.1 C149.2 C150.1 D45.1(K) U24.2(IN)
+6V_VSH: C128.1 C129.1 C133.2 C134.1 D39.1(K) U22.2(IN)
-5.0V_USH: C138.1 C142.2 D44.2(A) FB21.2 R6.2 TP3.1
-5.0V_VSH: C122.1 C126.2 D38.2(A) FB19.2 R19.2 TP6.1
-6V_USH: C139.2 C141.2 C146.1 C148.2 D43.2(A) U23.5(EN) U23.8(VIN)
-6V_VSH: C123.2 C125.2 C130.1 C132.2 D37.2(A) U21.5(EN) U21.8(VIN)
DGND: C5.1 C6.1 C7.1 C13.1 C14.1 C15.1 C16.2(-) U2.4(GND) U2.5(GND) U4.4(GND) U4.5(GND)
GND_USH: C7.2 C138.2 C139.1 C140.1 C141.1 C142.1 C144.2 C145.2 C146.2 C147.1 C148.1 C149.1 C150.2 C151.1 C152.2 C153.1 D1.1(C) D2.2(A) D44.1(K) D46.2(A) R103.1 T1.4 U23.3(NC) U23.4(GND) U23.9(TPAD) U24.1(GND)
GND_VSH: C15.2 C122.2 C123.1 C124.1 C125.1 C126.1 C128.2 C129.2 C130.2 C131.1 C132.1 C133.1 C134.2 C135.1 C136.2 C137.1 D3.1(C) D4.2(A) D38.1(K) D40.2(A) R101.1 T2.4 U21.3(NC) U21.4(GND) U21.9(TPAD) U22.1(GND)
NetC124_2: C124.2 U21.6(NR/SS)
NetC127_1: C127.1 R101.2 R102.1 U21.2(FB)
NetC127_2: C127.2 C131.2 FB19.1 R102.2 U21.1(OUT)
NetC137_2: C137.2 FB20.1 U22.3(OUT)
NetC140_2: C140.2 U23.6(NR/SS)
NetC143_1: C143.1 R103.2 R104.1 U23.2(FB)
NetC143_2: C143.2 C147.2 FB21.1 R104.2 U23.1(OUT)
NetC153_2: C153.2 FB22.1 U24.3(OUT)
NetD1_2: D1.2(A) R105.1
NetD2_1: D2.1(C) R6.1
NetD3_2: D3.2(A) R7.1
NetD4_1: D4.1(C) R19.1
NetD37_1: D37.1(K) D39.2(A) T2.6
NetD43_1: D43.1(K) D45.2(A) T1.6
NetT1_1: T1.1 U2.3(D2)
NetT1_3: T1.3 U2.1(D1)
NetT2_1: T2.1 U4.3(D2)
NetT2_3: T2.3 U4.1(D1)

Not connected (* = marked no-connect by the designer): T1 5; T2 5; U21 7(DNC); U22 4(NC) 5(NC); U23 7(DNC); U24 4(NC) 5(NC)

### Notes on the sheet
- (near R103) Feedback resistors are configured for -1.5V
- (near R101) Feedback resistors are configured for -1.5V

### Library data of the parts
C5 C13 C122 C125 C129 C130 C134 C136 C138 C141 C145 C146 C150 C152 = C0603C104K5RACTU: as C30 on sheet Pg4-Current  signal condtioning
C6 C14 C123 C128 C131-C133 C137 C139 C144 C147-C149 C153 = GMK325AB7106MM-T: as C27 on sheet Pg4-Current  signal condtioning
C7 C15 = 202R18W102KV4E: as C26 on sheet Pg6-Power supply 1
C16 = UUD1E220MCL1GS: as C28 on sheet Pg6-Power supply 1
C124 C127 C140 C143 = 06031C103JAT2A: CAP, CERM, 0.01uF, 100V, +/-5%, X7R, 0603; PartNumber: 06031C103J4Z4A; Manufacturer: AVX; Polarized: N; CompType: Capacitor; U/M: EA; Cap_F: 0.00000001; Tolerance_%: 5; ESR_Ohm: 0.098; Value1: 0.098 ohm; VDC_V: 100; TaMin_C: -55; TaMax_C: 125
C126 C135 C142 C151 = C2012X5R1H475K125AB: as C72 on sheet Pg6-Power supply 1
D1-D4 = LED_LG L29K-G2J1-24-Z: as D5 on sheet Pg6-Power supply 1
D37 D39 D43 D45 = MBR0520LT1G: as D21 on sheet Pg6-Power supply 1
D38 D40 D44 D46 = DFLZ6V2-7: as D22 on sheet Pg6-Power supply 1
FB19-FB22 = MMZ1608B102C: as FB7 on sheet Pg3-Microcontroller
R6 R7 R19 R105 = CRCW06033K90JNEA: as R21 on sheet Pg6-Power supply 1
R101 R103 = CRCW060311K5FKEA: as R94 on sheet Pg6-Power supply 1
R102 R104 = RC0603FR-073K16L: as R95 on sheet Pg6-Power supply 1
T1 T2 = TRNSFMR: as T3 on sheet Pg6-Power supply 1
TP3 TP6 = TP-040_RND: as TP11 on sheet Pg3-Microcontroller
U2 U4 = SN6501DBV: as U6 on sheet Pg6-Power supply 1
U21 U23 = TPS7A3001DGNR: as U15 on sheet Pg6-Power supply 1
U22 U24 = TLV70450DBV: as U16 on sheet Pg6-Power supply 1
